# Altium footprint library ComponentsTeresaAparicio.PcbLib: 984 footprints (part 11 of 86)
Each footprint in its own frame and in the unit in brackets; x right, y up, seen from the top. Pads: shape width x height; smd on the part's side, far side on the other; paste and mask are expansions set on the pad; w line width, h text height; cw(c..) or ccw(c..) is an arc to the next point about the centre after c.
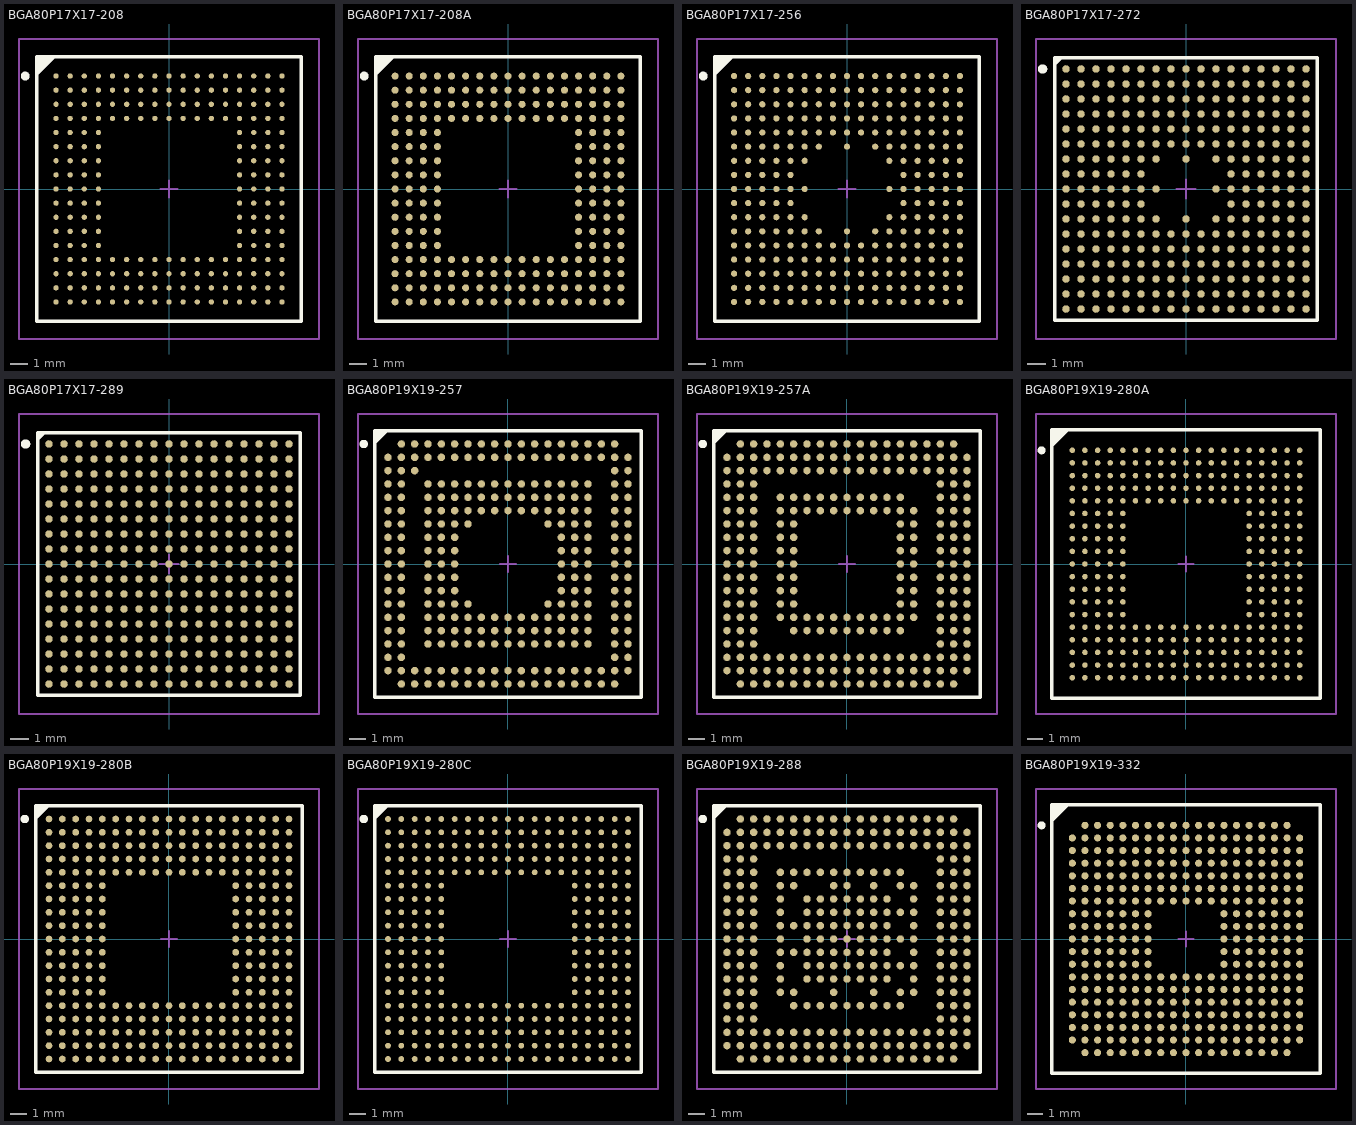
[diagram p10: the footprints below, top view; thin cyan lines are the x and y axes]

## BGA80P17X17-208 [mm] "208-Ball Ball Grid Array 0.8 mm Pitch"
height 1.1
pads (208):
  round 0.3 smd: A1(-6.4,6.4) A2(-5.6,6.4) A3(-4.8,6.4) A4(-4,6.4) A5(-3.2,6.4) A6(-2.4,6.4) A7(-1.6,6.4) A8(-0.8,6.4) A9(0,6.4) A10(0.8,6.4) A11(1.6,6.4) A12(2.4,6.4) A13(3.2,6.4) A14(4,6.4) A15(4.8,6.4) A16(5.6,6.4) A17(6.4,6.4) B1(-6.4,5.6) B2(-5.6,5.6) B3(-4.8,5.6) B4(-4,5.6) B5(-3.2,5.6) B6(-2.4,5.6) B7(-1.6,5.6) B8(-0.8,5.6) B9(0,5.6) B10(0.8,5.6) B11(1.6,5.6) B12(2.4,5.6) B13(3.2,5.6) B14(4,5.6) B15(4.8,5.6) B16(5.6,5.6) B17(6.4,5.6) C1(-6.4,4.8) C2(-5.6,4.8) C3(-4.8,4.8) C4(-4,4.8) C5(-3.2,4.8) C6(-2.4,4.8) C7(-1.6,4.8) C8(-0.8,4.8) C9(0,4.8) C10(0.8,4.8) C11(1.6,4.8) C12(2.4,4.8) C13(3.2,4.8) C14(4,4.8) C15(4.8,4.8) C16(5.6,4.8) C17(6.4,4.8) D1(-6.4,4) D2(-5.6,4) D3(-4.8,4) D4(-4,4) D5(-3.2,4) D6(-2.4,4) D7(-1.6,4) D8(-0.8,4) D9(0,4) D10(0.8,4) D11(1.6,4) D12(2.4,4) D13(3.2,4) D14(4,4) D15(4.8,4) D16(5.6,4) D17(6.4,4) E1(-6.4,3.2) E2(-5.6,3.2) E3(-4.8,3.2) E4(-4,3.2) E14(4,3.2) E15(4.8,3.2) E16(5.6,3.2) E17(6.4,3.2) F1(-6.4,2.4) F2(-5.6,2.4) F3(-4.8,2.4) F4(-4,2.4) F14(4,2.4) F15(4.8,2.4) F16(5.6,2.4) F17(6.4,2.4) G1(-6.4,1.6) G2(-5.6,1.6) G3(-4.8,1.6) G4(-4,1.6) G14(4,1.6) G15(4.8,1.6) G16(5.6,1.6) G17(6.4,1.6) H1(-6.4,0.8) H2(-5.6,0.8) H3(-4.8,0.8) H4(-4,0.8) H14(4,0.8) H15(4.8,0.8) H16(5.6,0.8) H17(6.4,0.8) J1(-6.4,0) J2(-5.6,0) J3(-4.8,0) J4(-4,0) J14(4,0) J15(4.8,0) J16(5.6,0) J17(6.4,0) K1(-6.4,-0.8) K2(-5.6,-0.8) K3(-4.8,-0.8) K4(-4,-0.8) K14(4,-0.8) K15(4.8,-0.8) K16(5.6,-0.8) K17(6.4,-0.8) L1(-6.4,-1.6) L2(-5.6,-1.6) L3(-4.8,-1.6) L4(-4,-1.6) L14(4,-1.6) L15(4.8,-1.6) L16(5.6,-1.6) L17(6.4,-1.6) M1(-6.4,-2.4) M2(-5.6,-2.4) M3(-4.8,-2.4) M4(-4,-2.4) M14(4,-2.4) M15(4.8,-2.4) M16(5.6,-2.4) M17(6.4,-2.4) N1(-6.4,-3.2) N2(-5.6,-3.2) N3(-4.8,-3.2) N4(-4,-3.2) N14(4,-3.2) N15(4.8,-3.2) N16(5.6,-3.2) N17(6.4,-3.2) P1(-6.4,-4) P2(-5.6,-4) P3(-4.8,-4) P4(-4,-4) P5(-3.2,-4) P6(-2.4,-4) P7(-1.6,-4) P8(-0.8,-4) P9(0,-4) P10(0.8,-4) P11(1.6,-4) P12(2.4,-4) P13(3.2,-4) P14(4,-4) P15(4.8,-4) P16(5.6,-4) P17(6.4,-4) R1(-6.4,-4.8) R2(-5.6,-4.8) R3(-4.8,-4.8) R4(-4,-4.8) R5(-3.2,-4.8) R6(-2.4,-4.8) R7(-1.6,-4.8) R8(-0.8,-4.8) R9(0,-4.8) R10(0.8,-4.8) R11(1.6,-4.8) R12(2.4,-4.8) R13(3.2,-4.8) R14(4,-4.8) R15(4.8,-4.8) R16(5.6,-4.8) R17(6.4,-4.8) T1(-6.4,-5.6) T2(-5.6,-5.6) T3(-4.8,-5.6) T4(-4,-5.6) T5(-3.2,-5.6) T6(-2.4,-5.6) T7(-1.6,-5.6) T8(-0.8,-5.6) T9(0,-5.6) T10(0.8,-5.6) T11(1.6,-5.6) T12(2.4,-5.6) T13(3.2,-5.6) T14(4,-5.6) T15(4.8,-5.6) T16(5.6,-5.6) T17(6.4,-5.6) U1(-6.4,-6.4) U2(-5.6,-6.4) U3(-4.8,-6.4) U4(-4,-6.4) U5(-3.2,-6.4) U6(-2.4,-6.4) U7(-1.6,-6.4) U8(-0.8,-6.4) U9(0,-6.4) U10(0.8,-6.4) U11(1.6,-6.4) U12(2.4,-6.4) U13(3.2,-6.4) U14(4,-6.4) U15(4.8,-6.4) U16(5.6,-6.4) U17(6.4,-6.4)
Top Overlay:
  circle w0.25: c-8.15,6.4 r0.125
  region: -6.5,7.5 -7.5,6.5 -7.5,7.5
  lines w0.2: -7.5,6.5 -6.5,7.5 ; -7.5,-7.5 7.5,-7.5 7.5,7.5 -7.5,7.5 -7.5,-7.5
Mechanical 13:
  lines w0.1: -7.5,-7.5 7.5,-7.5 7.5,7.5 -7.5,7.5 -7.5,-7.5
Mechanical 15:
  lines w0.1: -0.5,0 0.5,0 ; 0,-0.5 0,0.5 ; -8.5,-8.5 8.5,-8.5 8.5,8.5 -8.5,8.5 -8.5,-8.5
3D body: height 1.1, standoff 0, extent -7.5,-7.5 7.5,7.5

## BGA80P17X17-208A [mm] "208-Ball Plastic Thin Fine Pitch Ball Grid Array, TFBGA208"
height 1.2
pads (208):
  round 0.4 smd: A1(-6.4,6.4) A2(-5.6,6.4) A3(-4.8,6.4) A4(-4,6.4) A5(-3.2,6.4) A6(-2.4,6.4) A7(-1.6,6.4) A8(-0.8,6.4) A9(0,6.4) A10(0.8,6.4) A11(1.6,6.4) A12(2.4,6.4) A13(3.2,6.4) A14(4,6.4) A15(4.8,6.4) A16(5.6,6.4) A17(6.4,6.4) B1(-6.4,5.6) B2(-5.6,5.6) B3(-4.8,5.6) B4(-4,5.6) B5(-3.2,5.6) B6(-2.4,5.6) B7(-1.6,5.6) B8(-0.8,5.6) B9(0,5.6) B10(0.8,5.6) B11(1.6,5.6) B12(2.4,5.6) B13(3.2,5.6) B14(4,5.6) B15(4.8,5.6) B16(5.6,5.6) B17(6.4,5.6) C1(-6.4,4.8) C2(-5.6,4.8) C3(-4.8,4.8) C4(-4,4.8) C5(-3.2,4.8) C6(-2.4,4.8) C7(-1.6,4.8) C8(-0.8,4.8) C9(0,4.8) C10(0.8,4.8) C11(1.6,4.8) C12(2.4,4.8) C13(3.2,4.8) C14(4,4.8) C15(4.8,4.8) C16(5.6,4.8) C17(6.4,4.8) D1(-6.4,4) D2(-5.6,4) D3(-4.8,4) D4(-4,4) D5(-3.2,4) D6(-2.4,4) D7(-1.6,4) D8(-0.8,4) D9(0,4) D10(0.8,4) D11(1.6,4) D12(2.4,4) D13(3.2,4) D14(4,4) D15(4.8,4) D16(5.6,4) D17(6.4,4) E1(-6.4,3.2) E2(-5.6,3.2) E3(-4.8,3.2) E4(-4,3.2) E14(4,3.2) E15(4.8,3.2) E16(5.6,3.2) E17(6.4,3.2) F1(-6.4,2.4) F2(-5.6,2.4) F3(-4.8,2.4) F4(-4,2.4) F14(4,2.4) F15(4.8,2.4) F16(5.6,2.4) F17(6.4,2.4) G1(-6.4,1.6) G2(-5.6,1.6) G3(-4.8,1.6) G4(-4,1.6) G14(4,1.6) G15(4.8,1.6) G16(5.6,1.6) G17(6.4,1.6) H1(-6.4,0.8) H2(-5.6,0.8) H3(-4.8,0.8) H4(-4,0.8) H14(4,0.8) H15(4.8,0.8) H16(5.6,0.8) H17(6.4,0.8) J1(-6.4,0) J2(-5.6,0) J3(-4.8,0) J4(-4,0) J14(4,0) J15(4.8,0) J16(5.6,0) J17(6.4,0) K1(-6.4,-0.8) K2(-5.6,-0.8) K3(-4.8,-0.8) K4(-4,-0.8) K14(4,-0.8) K15(4.8,-0.8) K16(5.6,-0.8) K17(6.4,-0.8) L1(-6.4,-1.6) L2(-5.6,-1.6) L3(-4.8,-1.6) L4(-4,-1.6) L14(4,-1.6) L15(4.8,-1.6) L16(5.6,-1.6) L17(6.4,-1.6) M1(-6.4,-2.4) M2(-5.6,-2.4) M3(-4.8,-2.4) M4(-4,-2.4) M14(4,-2.4) M15(4.8,-2.4) M16(5.6,-2.4) M17(6.4,-2.4) N1(-6.4,-3.2) N2(-5.6,-3.2) N3(-4.8,-3.2) N4(-4,-3.2) N14(4,-3.2) N15(4.8,-3.2) N16(5.6,-3.2) N17(6.4,-3.2) P1(-6.4,-4) P2(-5.6,-4) P3(-4.8,-4) P4(-4,-4) P5(-3.2,-4) P6(-2.4,-4) P7(-1.6,-4) P8(-0.8,-4) P9(0,-4) P10(0.8,-4) P11(1.6,-4) P12(2.4,-4) P13(3.2,-4) P14(4,-4) P15(4.8,-4) P16(5.6,-4) P17(6.4,-4) R1(-6.4,-4.8) R2(-5.6,-4.8) R3(-4.8,-4.8) R4(-4,-4.8) R5(-3.2,-4.8) R6(-2.4,-4.8) R7(-1.6,-4.8) R8(-0.8,-4.8) R9(0,-4.8) R10(0.8,-4.8) R11(1.6,-4.8) R12(2.4,-4.8) R13(3.2,-4.8) R14(4,-4.8) R15(4.8,-4.8) R16(5.6,-4.8) R17(6.4,-4.8) T1(-6.4,-5.6) T2(-5.6,-5.6) T3(-4.8,-5.6) T4(-4,-5.6) T5(-3.2,-5.6) T6(-2.4,-5.6) T7(-1.6,-5.6) T8(-0.8,-5.6) T9(0,-5.6) T10(0.8,-5.6) T11(1.6,-5.6) T12(2.4,-5.6) T13(3.2,-5.6) T14(4,-5.6) T15(4.8,-5.6) T16(5.6,-5.6) T17(6.4,-5.6) U1(-6.4,-6.4) U2(-5.6,-6.4) U3(-4.8,-6.4) U4(-4,-6.4) U5(-3.2,-6.4) U6(-2.4,-6.4) U7(-1.6,-6.4) U8(-0.8,-6.4) U9(0,-6.4) U10(0.8,-6.4) U11(1.6,-6.4) U12(2.4,-6.4) U13(3.2,-6.4) U14(4,-6.4) U15(4.8,-6.4) U16(5.6,-6.4) U17(6.4,-6.4)
Top Overlay:
  circle w0.25: c-8.15,6.4 r0.125
  region: -6.5,7.5 -7.5,6.5 -7.5,7.5
  lines w0.2: -7.5,6.5 -6.5,7.5 ; -7.5,-7.5 7.5,-7.5 7.5,7.5 -7.5,7.5 -7.5,-7.5
Mechanical 13:
  lines w0.1: -7.5,-7.5 7.5,-7.5 7.5,7.5 -7.5,7.5 -7.5,-7.5
Mechanical 15:
  lines w0.1: -0.5,0 0.5,0 ; 0,-0.5 0,0.5 ; -8.5,-8.5 8.5,-8.5 8.5,8.5 -8.5,8.5 -8.5,-8.5
3D body: height 1.1, standoff 0, extent -7.5,-7.5 7.5,7.5

## BGA80P17X17-256 [mm] "BGA, 256-Leads, Body 15x15mm, Pitch 0.8mm"
height 1.25
pads (256):
  round 0.35 smd: A1(-6.4,6.4) A2(-5.6,6.4) A3(-4.8,6.4) A4(-4,6.4) A5(-3.2,6.4) A6(-2.4,6.4) A7(-1.6,6.4) A8(-0.8,6.4) A9(0,6.4) A10(0.8,6.4) A11(1.6,6.4) A12(2.4,6.4) A13(3.2,6.4) A14(4,6.4) A15(4.8,6.4) A16(5.6,6.4) A17(6.4,6.4) B1(-6.4,5.6) B2(-5.6,5.6) B3(-4.8,5.6) B4(-4,5.6) B5(-3.2,5.6) B6(-2.4,5.6) B7(-1.6,5.6) B8(-0.8,5.6) B9(0,5.6) B10(0.8,5.6) B11(1.6,5.6) B12(2.4,5.6) B13(3.2,5.6) B14(4,5.6) B15(4.8,5.6) B16(5.6,5.6) B17(6.4,5.6) C1(-6.4,4.8) C2(-5.6,4.8) C3(-4.8,4.8) C4(-4,4.8) C5(-3.2,4.8) C6(-2.4,4.8) C7(-1.6,4.8) C8(-0.8,4.8) C9(0,4.8) C10(0.8,4.8) C11(1.6,4.8) C12(2.4,4.8) C13(3.2,4.8) C14(4,4.8) C15(4.8,4.8) C16(5.6,4.8) C17(6.4,4.8) D1(-6.4,4) D2(-5.6,4) D3(-4.8,4) D4(-4,4) D5(-3.2,4) D6(-2.4,4) D7(-1.6,4) D8(-0.8,4) D9(0,4) D10(0.8,4) D11(1.6,4) D12(2.4,4) D13(3.2,4) D14(4,4) D15(4.8,4) D16(5.6,4) D17(6.4,4) E1(-6.4,3.2) E2(-5.6,3.2) E3(-4.8,3.2) E4(-4,3.2) E5(-3.2,3.2) E6(-2.4,3.2) E7(-1.6,3.2) E8(-0.8,3.2) E9(0,3.2) E10(0.8,3.2) E11(1.6,3.2) E12(2.4,3.2) E13(3.2,3.2) E14(4,3.2) E15(4.8,3.2) E16(5.6,3.2) E17(6.4,3.2) F1(-6.4,2.4) F2(-5.6,2.4) F3(-4.8,2.4) F4(-4,2.4) F5(-3.2,2.4) F6(-2.4,2.4) F7(-1.6,2.4) F9(0,2.4) F11(1.6,2.4) F12(2.4,2.4) F13(3.2,2.4) F14(4,2.4) F15(4.8,2.4) F16(5.6,2.4) F17(6.4,2.4) G1(-6.4,1.6) G2(-5.6,1.6) G3(-4.8,1.6) G4(-4,1.6) G5(-3.2,1.6) G6(-2.4,1.6) G12(2.4,1.6) G13(3.2,1.6) G14(4,1.6) G15(4.8,1.6) G16(5.6,1.6) G17(6.4,1.6) H1(-6.4,0.8) H2(-5.6,0.8) H3(-4.8,0.8) H4(-4,0.8) H5(-3.2,0.8) H13(3.2,0.8) H14(4,0.8) H15(4.8,0.8) H16(5.6,0.8) H17(6.4,0.8) J1(-6.4,0) J2(-5.6,0) J3(-4.8,0) J4(-4,0) J5(-3.2,0) J6(-2.4,0) J12(2.4,0) J13(3.2,0) J14(4,0) J15(4.8,0) J16(5.6,0) J17(6.4,0) K1(-6.4,-0.8) K2(-5.6,-0.8) K3(-4.8,-0.8) K4(-4,-0.8) K5(-3.2,-0.8) K13(3.2,-0.8) K14(4,-0.8) K15(4.8,-0.8) K16(5.6,-0.8) K17(6.4,-0.8) L1(-6.4,-1.6) L2(-5.6,-1.6) L3(-4.8,-1.6) L4(-4,-1.6) L5(-3.2,-1.6) L6(-2.4,-1.6) L12(2.4,-1.6) L13(3.2,-1.6) L14(4,-1.6) L15(4.8,-1.6) L16(5.6,-1.6) L17(6.4,-1.6) M1(-6.4,-2.4) M2(-5.6,-2.4) M3(-4.8,-2.4) M4(-4,-2.4) M5(-3.2,-2.4) M6(-2.4,-2.4) M7(-1.6,-2.4) M9(0,-2.4) M11(1.6,-2.4) M12(2.4,-2.4) M13(3.2,-2.4) M14(4,-2.4) M15(4.8,-2.4) M16(5.6,-2.4) M17(6.4,-2.4) N1(-6.4,-3.2) N2(-5.6,-3.2) N3(-4.8,-3.2) N4(-4,-3.2) N5(-3.2,-3.2) N6(-2.4,-3.2) N7(-1.6,-3.2) N8(-0.8,-3.2) N9(0,-3.2) N10(0.8,-3.2) N11(1.6,-3.2) N12(2.4,-3.2) N13(3.2,-3.2) N14(4,-3.2) N15(4.8,-3.2) N16(5.6,-3.2) N17(6.4,-3.2) P1(-6.4,-4) P2(-5.6,-4) P3(-4.8,-4) P4(-4,-4) P5(-3.2,-4) P6(-2.4,-4) P7(-1.6,-4) P8(-0.8,-4) P9(0,-4) P10(0.8,-4) P11(1.6,-4) P12(2.4,-4) P13(3.2,-4) P14(4,-4) P15(4.8,-4) P16(5.6,-4) P17(6.4,-4) R1(-6.4,-4.8) R2(-5.6,-4.8) R3(-4.8,-4.8) R4(-4,-4.8) R5(-3.2,-4.8) R6(-2.4,-4.8) R7(-1.6,-4.8) R8(-0.8,-4.8) R9(0,-4.8) R10(0.8,-4.8) R11(1.6,-4.8) R12(2.4,-4.8) R13(3.2,-4.8) R14(4,-4.8) R15(4.8,-4.8) R16(5.6,-4.8) R17(6.4,-4.8) T1(-6.4,-5.6) T2(-5.6,-5.6) T3(-4.8,-5.6) T4(-4,-5.6) T5(-3.2,-5.6) T6(-2.4,-5.6) T7(-1.6,-5.6) T8(-0.8,-5.6) T9(0,-5.6) T10(0.8,-5.6) T11(1.6,-5.6) T12(2.4,-5.6) T13(3.2,-5.6) T14(4,-5.6) T15(4.8,-5.6) T16(5.6,-5.6) T17(6.4,-5.6) U1(-6.4,-6.4) U2(-5.6,-6.4) U3(-4.8,-6.4) U4(-4,-6.4) U5(-3.2,-6.4) U6(-2.4,-6.4) U7(-1.6,-6.4) U8(-0.8,-6.4) U9(0,-6.4) U10(0.8,-6.4) U11(1.6,-6.4) U12(2.4,-6.4) U13(3.2,-6.4) U14(4,-6.4) U15(4.8,-6.4) U16(5.6,-6.4) U17(6.4,-6.4)
Top Overlay:
  circle w0.25: c-8.15,6.4 r0.125
  region: -6.5,7.5 -7.5,6.5 -7.5,7.5
  lines w0.2: -7.5,6.5 -6.5,7.5 ; -7.5,-7.5 7.5,-7.5 7.5,7.5 -7.5,7.5 -7.5,-7.5
Mechanical 13:
  lines w0.1: -7.5,-7.5 7.5,-7.5 7.5,7.5 -7.5,7.5 -7.5,-7.5
Mechanical 15:
  lines w0.1: -0.5,0 0.5,0 ; 0,-0.5 0,0.5 ; -8.5,-8.5 8.5,-8.5 8.5,8.5 -8.5,8.5 -8.5,-8.5
3D body: height 1.25, standoff 0, extent -7.5,-7.5 7.5,7.5

## BGA80P17X17-272 [mm] "272-Ball Ball Grid Array 0.8 mm Pitch"
height 1.16
pads (272):
  round 0.4 smd: A1(-6.4,6.4) A2(-5.6,6.4) A3(-4.8,6.4) A4(-4,6.4) A5(-3.2,6.4) A6(-2.4,6.4) A7(-1.6,6.4) A8(-0.8,6.4) A9(0,6.4) A10(0.8,6.4) A11(1.6,6.4) A12(2.4,6.4) A13(3.2,6.4) A14(4,6.4) A15(4.8,6.4) A16(5.6,6.4) A17(6.4,6.4) B1(-6.4,5.6) B2(-5.6,5.6) B3(-4.8,5.6) B4(-4,5.6) B5(-3.2,5.6) B6(-2.4,5.6) B7(-1.6,5.6) B8(-0.8,5.6) B9(0,5.6) B10(0.8,5.6) B11(1.6,5.6) B12(2.4,5.6) B13(3.2,5.6) B14(4,5.6) B15(4.8,5.6) B16(5.6,5.6) B17(6.4,5.6) C1(-6.4,4.8) C2(-5.6,4.8) C3(-4.8,4.8) C4(-4,4.8) C5(-3.2,4.8) C6(-2.4,4.8) C7(-1.6,4.8) C8(-0.8,4.8) C9(0,4.8) C10(0.8,4.8) C11(1.6,4.8) C12(2.4,4.8) C13(3.2,4.8) C14(4,4.8) C15(4.8,4.8) C16(5.6,4.8) C17(6.4,4.8) D1(-6.4,4) D2(-5.6,4) D3(-4.8,4) D4(-4,4) D5(-3.2,4) D6(-2.4,4) D7(-1.6,4) D8(-0.8,4) D9(0,4) D10(0.8,4) D11(1.6,4) D12(2.4,4) D13(3.2,4) D14(4,4) D15(4.8,4) D16(5.6,4) D17(6.4,4) E1(-6.4,3.2) E2(-5.6,3.2) E3(-4.8,3.2) E4(-4,3.2) E5(-3.2,3.2) E6(-2.4,3.2) E7(-1.6,3.2) E8(-0.8,3.2) E9(0,3.2) E10(0.8,3.2) E11(1.6,3.2) E12(2.4,3.2) E13(3.2,3.2) E14(4,3.2) E15(4.8,3.2) E16(5.6,3.2) E17(6.4,3.2) F1(-6.4,2.4) F2(-5.6,2.4) F3(-4.8,2.4) F4(-4,2.4) F5(-3.2,2.4) F6(-2.4,2.4) F7(-1.6,2.4) F8(-0.8,2.4) F9(0,2.4) F10(0.8,2.4) F11(1.6,2.4) F12(2.4,2.4) F13(3.2,2.4) F14(4,2.4) F15(4.8,2.4) F16(5.6,2.4) F17(6.4,2.4) G1(-6.4,1.6) G2(-5.6,1.6) G3(-4.8,1.6) G4(-4,1.6) G5(-3.2,1.6) G6(-2.4,1.6) G7(-1.6,1.6) G9(0,1.6) G11(1.6,1.6) G12(2.4,1.6) G13(3.2,1.6) G14(4,1.6) G15(4.8,1.6) G16(5.6,1.6) G17(6.4,1.6) H1(-6.4,0.8) H2(-5.6,0.8) H3(-4.8,0.8) H4(-4,0.8) H5(-3.2,0.8) H6(-2.4,0.8) H12(2.4,0.8) H13(3.2,0.8) H14(4,0.8) H15(4.8,0.8) H16(5.6,0.8) H17(6.4,0.8) J1(-6.4,0) J2(-5.6,0) J3(-4.8,0) J4(-4,0) J5(-3.2,0) J6(-2.4,0) J7(-1.6,0) J11(1.6,0) J12(2.4,0) J13(3.2,0) J14(4,0) J15(4.8,0) J16(5.6,0) J17(6.4,0) K1(-6.4,-0.8) K2(-5.6,-0.8) K3(-4.8,-0.8) K4(-4,-0.8) K5(-3.2,-0.8) K6(-2.4,-0.8) K12(2.4,-0.8) K13(3.2,-0.8) K14(4,-0.8) K15(4.8,-0.8) K16(5.6,-0.8) K17(6.4,-0.8) L1(-6.4,-1.6) L2(-5.6,-1.6) L3(-4.8,-1.6) L4(-4,-1.6) L5(-3.2,-1.6) L6(-2.4,-1.6) L7(-1.6,-1.6) L9(0,-1.6) L11(1.6,-1.6) L12(2.4,-1.6) L13(3.2,-1.6) L14(4,-1.6) L15(4.8,-1.6) L16(5.6,-1.6) L17(6.4,-1.6) M1(-6.4,-2.4) M2(-5.6,-2.4) M3(-4.8,-2.4) M4(-4,-2.4) M5(-3.2,-2.4) M6(-2.4,-2.4) M7(-1.6,-2.4) M8(-0.8,-2.4) M9(0,-2.4) M10(0.8,-2.4) M11(1.6,-2.4) M12(2.4,-2.4) M13(3.2,-2.4) M14(4,-2.4) M15(4.8,-2.4) M16(5.6,-2.4) M17(6.4,-2.4) N1(-6.4,-3.2) N2(-5.6,-3.2) N3(-4.8,-3.2) N4(-4,-3.2) N5(-3.2,-3.2) N6(-2.4,-3.2) N7(-1.6,-3.2) N8(-0.8,-3.2) N9(0,-3.2) N10(0.8,-3.2) N11(1.6,-3.2) N12(2.4,-3.2) N13(3.2,-3.2) N14(4,-3.2) N15(4.8,-3.2) N16(5.6,-3.2) N17(6.4,-3.2) P1(-6.4,-4) P2(-5.6,-4) P3(-4.8,-4) P4(-4,-4) P5(-3.2,-4) P6(-2.4,-4) P7(-1.6,-4) P8(-0.8,-4) P9(0,-4) P10(0.8,-4) P11(1.6,-4) P12(2.4,-4) P13(3.2,-4) P14(4,-4) P15(4.8,-4) P16(5.6,-4) P17(6.4,-4) R1(-6.4,-4.8) R2(-5.6,-4.8) R3(-4.8,-4.8) R4(-4,-4.8) R5(-3.2,-4.8) R6(-2.4,-4.8) R7(-1.6,-4.8) R8(-0.8,-4.8) R9(0,-4.8) R10(0.8,-4.8) R11(1.6,-4.8) R12(2.4,-4.8) R13(3.2,-4.8) R14(4,-4.8) R15(4.8,-4.8) R16(5.6,-4.8) R17(6.4,-4.8) T1(-6.4,-5.6) T2(-5.6,-5.6) T3(-4.8,-5.6) T4(-4,-5.6) T5(-3.2,-5.6) T6(-2.4,-5.6) T7(-1.6,-5.6) T8(-0.8,-5.6) T9(0,-5.6) T10(0.8,-5.6) T11(1.6,-5.6) T12(2.4,-5.6) T13(3.2,-5.6) T14(4,-5.6) T15(4.8,-5.6) T16(5.6,-5.6) T17(6.4,-5.6) U1(-6.4,-6.4) U2(-5.6,-6.4) U3(-4.8,-6.4) U4(-4,-6.4) U5(-3.2,-6.4) U6(-2.4,-6.4) U7(-1.6,-6.4) U8(-0.8,-6.4) U9(0,-6.4) U10(0.8,-6.4) U11(1.6,-6.4) U12(2.4,-6.4) U13(3.2,-6.4) U14(4,-6.4) U15(4.8,-6.4) U16(5.6,-6.4) U17(6.4,-6.4)
Top Overlay:
  circle w0.25: c-7.65,6.4 r0.125
  region: -6.649,7 -7,6.649 -7,7
  lines w0.2: -7,6.649 -6.649,7 ; -7,-7 7,-7 7,7 -7,7 -7,-7
Mechanical 13:
  lines w0.1: -7,-7 7,-7 7,7 -7,7 -7,-7
Mechanical 15:
  lines w0.1: -0.5,0 0.5,0 ; 0,-0.5 0,0.5 ; -8,-8 8,-8 8,8 -8,8 -8,-8
3D body: height 1.16, standoff 0, extent -7,-7 7,7

## BGA80P17X17-289 [mm] "BGA, 289-Leads, Body 14x14mm, Pitch 0.8mm"
height 1.22
pads (289):
  round 0.4 smd: A1(-6.4,6.4) A2(-5.6,6.4) A3(-4.8,6.4) A4(-4,6.4) A5(-3.2,6.4) A6(-2.4,6.4) A7(-1.6,6.4) A8(-0.8,6.4) A9(0,6.4) A10(0.8,6.4) A11(1.6,6.4) A12(2.4,6.4) A13(3.2,6.4) A14(4,6.4) A15(4.8,6.4) A16(5.6,6.4) A17(6.4,6.4) B1(-6.4,5.6) B2(-5.6,5.6) B3(-4.8,5.6) B4(-4,5.6) B5(-3.2,5.6) B6(-2.4,5.6) B7(-1.6,5.6) B8(-0.8,5.6) B9(0,5.6) B10(0.8,5.6) B11(1.6,5.6) B12(2.4,5.6) B13(3.2,5.6) B14(4,5.6) B15(4.8,5.6) B16(5.6,5.6) B17(6.4,5.6) C1(-6.4,4.8) C2(-5.6,4.8) C3(-4.8,4.8) C4(-4,4.8) C5(-3.2,4.8) C6(-2.4,4.8) C7(-1.6,4.8) C8(-0.8,4.8) C9(0,4.8) C10(0.8,4.8) C11(1.6,4.8) C12(2.4,4.8) C13(3.2,4.8) C14(4,4.8) C15(4.8,4.8) C16(5.6,4.8) C17(6.4,4.8) D1(-6.4,4) D2(-5.6,4) D3(-4.8,4) D4(-4,4) D5(-3.2,4) D6(-2.4,4) D7(-1.6,4) D8(-0.8,4) D9(0,4) D10(0.8,4) D11(1.6,4) D12(2.4,4) D13(3.2,4) D14(4,4) D15(4.8,4) D16(5.6,4) D17(6.4,4) E1(-6.4,3.2) E2(-5.6,3.2) E3(-4.8,3.2) E4(-4,3.2) E5(-3.2,3.2) E6(-2.4,3.2) E7(-1.6,3.2) E8(-0.8,3.2) E9(0,3.2) E10(0.8,3.2) E11(1.6,3.2) E12(2.4,3.2) E13(3.2,3.2) E14(4,3.2) E15(4.8,3.2) E16(5.6,3.2) E17(6.4,3.2) F1(-6.4,2.4) F2(-5.6,2.4) F3(-4.8,2.4) F4(-4,2.4) F5(-3.2,2.4) F6(-2.4,2.4) F7(-1.6,2.4) F8(-0.8,2.4) F9(0,2.4) F10(0.8,2.4) F11(1.6,2.4) F12(2.4,2.4) F13(3.2,2.4) F14(4,2.4) F15(4.8,2.4) F16(5.6,2.4) F17(6.4,2.4) G1(-6.4,1.6) G2(-5.6,1.6) G3(-4.8,1.6) G4(-4,1.6) G5(-3.2,1.6) G6(-2.4,1.6) G7(-1.6,1.6) G8(-0.8,1.6) G9(0,1.6) G10(0.8,1.6) G11(1.6,1.6) G12(2.4,1.6) G13(3.2,1.6) G14(4,1.6) G15(4.8,1.6) G16(5.6,1.6) G17(6.4,1.6) H1(-6.4,0.8) H2(-5.6,0.8) H3(-4.8,0.8) H4(-4,0.8) H5(-3.2,0.8) H6(-2.4,0.8) H7(-1.6,0.8) H8(-0.8,0.8) H9(0,0.8) H10(0.8,0.8) H11(1.6,0.8) H12(2.4,0.8) H13(3.2,0.8) H14(4,0.8) H15(4.8,0.8) H16(5.6,0.8) H17(6.4,0.8) J1(-6.4,0) J2(-5.6,0) J3(-4.8,0) J4(-4,0) J5(-3.2,0) J6(-2.4,0) J7(-1.6,0) J8(-0.8,0) J9(0,0) J10(0.8,0) J11(1.6,0) J12(2.4,0) J13(3.2,0) J14(4,0) J15(4.8,0) J16(5.6,0) J17(6.4,0) K1(-6.4,-0.8) K2(-5.6,-0.8) K3(-4.8,-0.8) K4(-4,-0.8) K5(-3.2,-0.8) K6(-2.4,-0.8) K7(-1.6,-0.8) K8(-0.8,-0.8) K9(0,-0.8) K10(0.8,-0.8) K11(1.6,-0.8) K12(2.4,-0.8) K13(3.2,-0.8) K14(4,-0.8) K15(4.8,-0.8) K16(5.6,-0.8) K17(6.4,-0.8) L1(-6.4,-1.6) L2(-5.6,-1.6) L3(-4.8,-1.6) L4(-4,-1.6) L5(-3.2,-1.6) L6(-2.4,-1.6) L7(-1.6,-1.6) L8(-0.8,-1.6) L9(0,-1.6) L10(0.8,-1.6) L11(1.6,-1.6) L12(2.4,-1.6) L13(3.2,-1.6) L14(4,-1.6) L15(4.8,-1.6) L16(5.6,-1.6) L17(6.4,-1.6) M1(-6.4,-2.4) M2(-5.6,-2.4) M3(-4.8,-2.4) M4(-4,-2.4) M5(-3.2,-2.4) M6(-2.4,-2.4) M7(-1.6,-2.4) M8(-0.8,-2.4) M9(0,-2.4) M10(0.8,-2.4) M11(1.6,-2.4) M12(2.4,-2.4) M13(3.2,-2.4) M14(4,-2.4) M15(4.8,-2.4) M16(5.6,-2.4) M17(6.4,-2.4) N1(-6.4,-3.2) N2(-5.6,-3.2) N3(-4.8,-3.2) N4(-4,-3.2) N5(-3.2,-3.2) N6(-2.4,-3.2) N7(-1.6,-3.2) N8(-0.8,-3.2) N9(0,-3.2) N10(0.8,-3.2) N11(1.6,-3.2) N12(2.4,-3.2) N13(3.2,-3.2) N14(4,-3.2) N15(4.8,-3.2) N16(5.6,-3.2) N17(6.4,-3.2) P1(-6.4,-4) P2(-5.6,-4) P3(-4.8,-4) P4(-4,-4) P5(-3.2,-4) P6(-2.4,-4) P7(-1.6,-4) P8(-0.8,-4) P9(0,-4) P10(0.8,-4) P11(1.6,-4) P12(2.4,-4) P13(3.2,-4) P14(4,-4) P15(4.8,-4) P16(5.6,-4) P17(6.4,-4) R1(-6.4,-4.8) R2(-5.6,-4.8) R3(-4.8,-4.8) R4(-4,-4.8) R5(-3.2,-4.8) R6(-2.4,-4.8) R7(-1.6,-4.8) R8(-0.8,-4.8) R9(0,-4.8) R10(0.8,-4.8) R11(1.6,-4.8) R12(2.4,-4.8) R13(3.2,-4.8) R14(4,-4.8) R15(4.8,-4.8) R16(5.6,-4.8) R17(6.4,-4.8) T1(-6.4,-5.6) T2(-5.6,-5.6) T3(-4.8,-5.6) T4(-4,-5.6) T5(-3.2,-5.6) T6(-2.4,-5.6) T7(-1.6,-5.6) T8(-0.8,-5.6) T9(0,-5.6) T10(0.8,-5.6) T11(1.6,-5.6) T12(2.4,-5.6) T13(3.2,-5.6) T14(4,-5.6) T15(4.8,-5.6) T16(5.6,-5.6) T17(6.4,-5.6) U1(-6.4,-6.4) U2(-5.6,-6.4) U3(-4.8,-6.4) U4(-4,-6.4) U5(-3.2,-6.4) U6(-2.4,-6.4) U7(-1.6,-6.4) U8(-0.8,-6.4) U9(0,-6.4) U10(0.8,-6.4) U11(1.6,-6.4) U12(2.4,-6.4) U13(3.2,-6.4) U14(4,-6.4) U15(4.8,-6.4) U16(5.6,-6.4) U17(6.4,-6.4)
Top Overlay:
  circle w0.25: c-7.65,6.4 r0.125
  region: -6.649,7 -7,6.649 -7,7
  lines w0.2: -7,6.649 -6.649,7 ; -7,-7 -7,7 7,7 7,-7 -7,-7
Mechanical 13:
  lines w0.1: -7,-7 -7,7 7,7 7,-7 -7,-7
Mechanical 15:
  lines w0.1: -0.5,0 0.5,0 ; 0,-0.5 0,0.5 ; -8,-8 -8,8 8,8 8,-8 -8,-8
3D body: height 1.22, standoff 0, extent -6.999,-6.999 6.999,6.999

## BGA80P19X19-257 [mm] "257-Ball Ball Grid Array 0.8 mm Pitch"
height 1.4
pads (257):
  round 0.45 smd: A2(-6.4,7.2) A3(-5.6,7.2) A4(-4.8,7.2) A5(-4,7.2) A6(-3.2,7.2) A7(-2.4,7.2) A8(-1.6,7.2) A9(-0.8,7.2) A10(0,7.2) A11(0.8,7.2) A12(1.6,7.2) A13(2.4,7.2) A14(3.2,7.2) A15(4,7.2) A16(4.8,7.2) A17(5.6,7.2) A18(6.4,7.2) B1(-7.2,6.4) B2(-6.4,6.4) B3(-5.6,6.4) B4(-4.8,6.4) B5(-4,6.4) B6(-3.2,6.4) B7(-2.4,6.4) B8(-1.6,6.4) B9(-0.8,6.4) B10(0,6.4) B11(0.8,6.4) B12(1.6,6.4) B13(2.4,6.4) B14(3.2,6.4) B15(4,6.4) B16(4.8,6.4) B17(5.6,6.4) B18(6.4,6.4) B19(7.2,6.4) C1(-7.2,5.6) C2(-6.4,5.6) C3(-5.6,5.6) C18(6.4,5.6) C19(7.2,5.6) D1(-7.2,4.8) D2(-6.4,4.8) D4(-4.8,4.8) D5(-4,4.8) D6(-3.2,4.8) D7(-2.4,4.8) D8(-1.6,4.8) D9(-0.8,4.8) D10(0,4.8) D11(0.8,4.8) D12(1.6,4.8) D13(2.4,4.8) D14(3.2,4.8) D15(4,4.8) D16(4.8,4.8) D18(6.4,4.8) D19(7.2,4.8) E1(-7.2,4) E2(-6.4,4) E4(-4.8,4) E5(-4,4) E6(-3.2,4) E7(-2.4,4) E8(-1.6,4) E9(-0.8,4) E10(0,4) E11(0.8,4) E12(1.6,4) E13(2.4,4) E14(3.2,4) E15(4,4) E16(4.8,4) E18(6.4,4) E19(7.2,4) F1(-7.2,3.2) F2(-6.4,3.2) F4(-4.8,3.2) F5(-4,3.2) F6(-3.2,3.2) F7(-2.4,3.2) F8(-1.6,3.2) F9(-0.8,3.2) F10(0,3.2) F11(0.8,3.2) F12(1.6,3.2) F13(2.4,3.2) F14(3.2,3.2) F15(4,3.2) F16(4.8,3.2) F18(6.4,3.2) F19(7.2,3.2) G1(-7.2,2.4) G2(-6.4,2.4) G4(-4.8,2.4) G5(-4,2.4) G6(-3.2,2.4) G7(-2.4,2.4) G13(2.4,2.4) G14(3.2,2.4) G15(4,2.4) G16(4.8,2.4) G18(6.4,2.4) G19(7.2,2.4) H1(-7.2,1.6) H2(-6.4,1.6) H4(-4.8,1.6) H5(-4,1.6) H6(-3.2,1.6) H14(3.2,1.6) H15(4,1.6) H16(4.8,1.6) H18(6.4,1.6) H19(7.2,1.6) J1(-7.2,0.8) J2(-6.4,0.8) J4(-4.8,0.8) J5(-4,0.8) J6(-3.2,0.8) J14(3.2,0.8) J15(4,0.8) J16(4.8,0.8) J18(6.4,0.8) J19(7.2,0.8) K1(-7.2,0) K2(-6.4,0) K4(-4.8,0) K5(-4,0) K6(-3.2,0) K14(3.2,0) K15(4,0) K16(4.8,0) K18(6.4,0) K19(7.2,0) L1(-7.2,-0.8) L2(-6.4,-0.8) L4(-4.8,-0.8) L5(-4,-0.8) L6(-3.2,-0.8) L14(3.2,-0.8) L15(4,-0.8) L16(4.8,-0.8) L18(6.4,-0.8) L19(7.2,-0.8) M1(-7.2,-1.6) M2(-6.4,-1.6) M4(-4.8,-1.6) M5(-4,-1.6) M6(-3.2,-1.6) M14(3.2,-1.6) M15(4,-1.6) M16(4.8,-1.6) M18(6.4,-1.6) M19(7.2,-1.6) N1(-7.2,-2.4) N2(-6.4,-2.4) N4(-4.8,-2.4) N5(-4,-2.4) N6(-3.2,-2.4) N7(-2.4,-2.4) N13(2.4,-2.4) N14(3.2,-2.4) N15(4,-2.4) N16(4.8,-2.4) N18(6.4,-2.4) N19(7.2,-2.4) P1(-7.2,-3.2) P2(-6.4,-3.2) P4(-4.8,-3.2) P5(-4,-3.2) P6(-3.2,-3.2) P7(-2.4,-3.2) P8(-1.6,-3.2) P9(-0.8,-3.2) P10(0,-3.2) P11(0.8,-3.2) P12(1.6,-3.2) P13(2.4,-3.2) P14(3.2,-3.2) P15(4,-3.2) P16(4.8,-3.2) P18(6.4,-3.2) P19(7.2,-3.2) R1(-7.2,-4) R2(-6.4,-4) R4(-4.8,-4) R5(-4,-4) R6(-3.2,-4) R7(-2.4,-4) R8(-1.6,-4) R9(-0.8,-4) R10(0,-4) R11(0.8,-4) R12(1.6,-4) R13(2.4,-4) R14(3.2,-4) R15(4,-4) R16(4.8,-4) R18(6.4,-4) R19(7.2,-4) T1(-7.2,-4.8) T2(-6.4,-4.8) T4(-4.8,-4.8) T5(-4,-4.8) T6(-3.2,-4.8) T7(-2.4,-4.8) T8(-1.6,-4.8) T9(-0.8,-4.8) T10(0,-4.8) T11(0.8,-4.8) T12(1.6,-4.8) T13(2.4,-4.8) T14(3.2,-4.8) T15(4,-4.8) T16(4.8,-4.8) T18(6.4,-4.8) T19(7.2,-4.8) U1(-7.2,-5.6) U2(-6.4,-5.6) U18(6.4,-5.6) U19(7.2,-5.6) V1(-7.2,-6.4) V2(-6.4,-6.4) V3(-5.6,-6.4) V4(-4.8,-6.4) V5(-4,-6.4) V6(-3.2,-6.4) V7(-2.4,-6.4) V8(-1.6,-6.4) V9(-0.8,-6.4) V10(0,-6.4) V11(0.8,-6.4) V12(1.6,-6.4) V13(2.4,-6.4) V14(3.2,-6.4) V15(4,-6.4) V16(4.8,-6.4) V17(5.6,-6.4) V18(6.4,-6.4) V19(7.2,-6.4) W2(-6.4,-7.2) W3(-5.6,-7.2) W4(-4.8,-7.2) W5(-4,-7.2) W6(-3.2,-7.2) W7(-2.4,-7.2) W8(-1.6,-7.2) W9(-0.8,-7.2) W10(0,-7.2) W11(0.8,-7.2) W12(1.6,-7.2) W13(2.4,-7.2) W14(3.2,-7.2) W15(4,-7.2) W16(4.8,-7.2) W17(5.6,-7.2) W18(6.4,-7.2)
Top Overlay:
  circle w0.25: c-8.65,7.2 r0.125
  region: -7.284,8 -8,7.284 -8,8
  lines w0.2: -8,7.284 -7.284,8 ; -8,-8 -8,8 8,8 8,-8 -8,-8
Mechanical 13:
  lines w0.1: -8,-8 -8,8 8,8 8,-8 -8,-8
Mechanical 15:
  lines w0.1: -0.5,0 0.5,0 ; 0,-0.5 0,0.5 ; -9,-9 -9,9 9,9 9,-9 -9,-9
3D body: height 1.4, standoff 0, extent -8,-8 8,8

## BGA80P19X19-257A [mm] "257-Ball Plastic Ball Grid Array 0.8 mm Pitch"
height 1.4
pads (257):
  round 0.45 smd: A2(-6.4,7.2) A3(-5.6,7.2) A4(-4.8,7.2) A5(-4,7.2) A6(-3.2,7.2) A7(-2.4,7.2) A8(-1.6,7.2) A9(-0.8,7.2) A10(0,7.2) A11(0.8,7.2) A12(1.6,7.2) A13(2.4,7.2) A14(3.2,7.2) A15(4,7.2) A16(4.8,7.2) A17(5.6,7.2) A18(6.4,7.2) B1(-7.2,6.4) B2(-6.4,6.4) B3(-5.6,6.4) B4(-4.8,6.4) B5(-4,6.4) B6(-3.2,6.4) B7(-2.4,6.4) B8(-1.6,6.4) B9(-0.8,6.4) B10(0,6.4) B11(0.8,6.4) B12(1.6,6.4) B13(2.4,6.4) B14(3.2,6.4) B15(4,6.4) B16(4.8,6.4) B17(5.6,6.4) B18(6.4,6.4) B19(7.2,6.4) C1(-7.2,5.6) C2(-6.4,5.6) C3(-5.6,5.6) C4(-4.8,5.6) C5(-4,5.6) C6(-3.2,5.6) C7(-2.4,5.6) C8(-1.6,5.6) C9(-0.8,5.6) C10(0,5.6) C11(0.8,5.6) C12(1.6,5.6) C13(2.4,5.6) C14(3.2,5.6) C15(4,5.6) C16(4.8,5.6) C17(5.6,5.6) C18(6.4,5.6) C19(7.2,5.6) D1(-7.2,4.8) D2(-6.4,4.8) D3(-5.6,4.8) D17(5.6,4.8) D18(6.4,4.8) D19(7.2,4.8) E1(-7.2,4) E2(-6.4,4) E3(-5.6,4) E5(-4,4) E6(-3.2,4) E7(-2.4,4) E8(-1.6,4) E9(-0.8,4) E10(0,4) E11(0.8,4) E12(1.6,4) E13(2.4,4) E14(3.2,4) E17(5.6,4) E18(6.4,4) E19(7.2,4) F1(-7.2,3.2) F2(-6.4,3.2) F3(-5.6,3.2) F5(-4,3.2) F6(-3.2,3.2) F7(-2.4,3.2) F8(-1.6,3.2) F9(-0.8,3.2) F10(0,3.2) F11(0.8,3.2) F12(1.6,3.2) F13(2.4,3.2) F14(3.2,3.2) F15(4,3.2) F17(5.6,3.2) F18(6.4,3.2) F19(7.2,3.2) G1(-7.2,2.4) G2(-6.4,2.4) G3(-5.6,2.4) G5(-4,2.4) G6(-3.2,2.4) G14(3.2,2.4) G15(4,2.4) G17(5.6,2.4) G18(6.4,2.4) G19(7.2,2.4) H1(-7.2,1.6) H2(-6.4,1.6) H3(-5.6,1.6) H5(-4,1.6) H6(-3.2,1.6) H14(3.2,1.6) H15(4,1.6) H17(5.6,1.6) H18(6.4,1.6) H19(7.2,1.6) J1(-7.2,0.8) J2(-6.4,0.8) J3(-5.6,0.8) J5(-4,0.8) J6(-3.2,0.8) J14(3.2,0.8) J15(4,0.8) J17(5.6,0.8) J18(6.4,0.8) J19(7.2,0.8) K1(-7.2,0) K2(-6.4,0) K3(-5.6,0) K5(-4,0) K6(-3.2,0) K14(3.2,0) K15(4,0) K17(5.6,0) K18(6.4,0) K19(7.2,0) L1(-7.2,-0.8) L2(-6.4,-0.8) L3(-5.6,-0.8) L5(-4,-0.8) L6(-3.2,-0.8) L14(3.2,-0.8) L15(4,-0.8) L17(5.6,-0.8) L18(6.4,-0.8) L19(7.2,-0.8) M1(-7.2,-1.6) M2(-6.4,-1.6) M3(-5.6,-1.6) M5(-4,-1.6) M6(-3.2,-1.6) M14(3.2,-1.6) M15(4,-1.6) M17(5.6,-1.6) M18(6.4,-1.6) M19(7.2,-1.6) N1(-7.2,-2.4) N2(-6.4,-2.4) N3(-5.6,-2.4) N5(-4,-2.4) N6(-3.2,-2.4) N14(3.2,-2.4) N15(4,-2.4) N17(5.6,-2.4) N18(6.4,-2.4) N19(7.2,-2.4) P1(-7.2,-3.2) P2(-6.4,-3.2) P3(-5.6,-3.2) P5(-4,-3.2) P6(-3.2,-3.2) P7(-2.4,-3.2) P8(-1.6,-3.2) P9(-0.8,-3.2) P10(0,-3.2) P11(0.8,-3.2) P12(1.6,-3.2) P13(2.4,-3.2) P14(3.2,-3.2) P15(4,-3.2) P17(5.6,-3.2) P18(6.4,-3.2) P19(7.2,-3.2) R1(-7.2,-4) R2(-6.4,-4) R3(-5.6,-4) R6(-3.2,-4) R7(-2.4,-4) R8(-1.6,-4) R9(-0.8,-4) R10(0,-4) R11(0.8,-4) R12(1.6,-4) R13(2.4,-4) R14(3.2,-4) R17(5.6,-4) R18(6.4,-4) R19(7.2,-4) T1(-7.2,-4.8) T2(-6.4,-4.8) T3(-5.6,-4.8) T17(5.6,-4.8) T18(6.4,-4.8) T19(7.2,-4.8) U1(-7.2,-5.6) U2(-6.4,-5.6) U3(-5.6,-5.6) U4(-4.8,-5.6) U5(-4,-5.6) U6(-3.2,-5.6) U7(-2.4,-5.6) U8(-1.6,-5.6) U9(-0.8,-5.6) U10(0,-5.6) U11(0.8,-5.6) U12(1.6,-5.6) U13(2.4,-5.6) U14(3.2,-5.6) U15(4,-5.6) U16(4.8,-5.6) U17(5.6,-5.6) U18(6.4,-5.6) U19(7.2,-5.6) V1(-7.2,-6.4) V2(-6.4,-6.4) V3(-5.6,-6.4) V4(-4.8,-6.4) V5(-4,-6.4) V6(-3.2,-6.4) V7(-2.4,-6.4) V8(-1.6,-6.4) V9(-0.8,-6.4) V10(0,-6.4) V11(0.8,-6.4) V12(1.6,-6.4) V13(2.4,-6.4) V14(3.2,-6.4) V15(4,-6.4) V16(4.8,-6.4) V17(5.6,-6.4) V18(6.4,-6.4) V19(7.2,-6.4) W2(-6.4,-7.2) W3(-5.6,-7.2) W4(-4.8,-7.2) W5(-4,-7.2) W6(-3.2,-7.2) W7(-2.4,-7.2) W8(-1.6,-7.2) W9(-0.8,-7.2) W10(0,-7.2) W11(0.8,-7.2) W12(1.6,-7.2) W13(2.4,-7.2) W14(3.2,-7.2) W15(4,-7.2) W16(4.8,-7.2) W17(5.6,-7.2) W18(6.4,-7.2)
Top Overlay:
  circle w0.25: c-8.65,7.2 r0.125
  region: -7.284,8 -8,7.284 -8,8
  lines w0.2: -8,7.284 -7.284,8 ; -8,-8 -8,8 8,8 8,-8 -8,-8
Mechanical 13:
  lines w0.1: -8,-8 -8,8 8,8 8,-8 -8,-8
Mechanical 15:
  lines w0.1: -0.5,0 0.5,0 ; 0,-0.5 0,0.5 ; -9,-9 -9,9 9,9 9,-9 -9,-9
3D body: height 1.4, standoff 0, extent -8,-8 8,8

## BGA80P19X19-280A [mm] "280-Ball Ball Grid Array 0.8 mm Pitch"
height 1.5
pads (280):
  round 0.35 smd: A1(-7.2,7.2) A2(-6.4,7.2) A3(-5.6,7.2) A4(-4.8,7.2) A5(-4,7.2) A6(-3.2,7.2) A7(-2.4,7.2) A8(-1.6,7.2) A9(-0.8,7.2) A10(0,7.2) A11(0.8,7.2) A12(1.6,7.2) A13(2.4,7.2) A14(3.2,7.2) A15(4,7.2) A16(4.8,7.2) A17(5.6,7.2) A18(6.4,7.2) A19(7.2,7.2) B1(-7.2,6.4) B2(-6.4,6.4) B3(-5.6,6.4) B4(-4.8,6.4) B5(-4,6.4) B6(-3.2,6.4) B7(-2.4,6.4) B8(-1.6,6.4) B9(-0.8,6.4) B10(0,6.4) B11(0.8,6.4) B12(1.6,6.4) B13(2.4,6.4) B14(3.2,6.4) B15(4,6.4) B16(4.8,6.4) B17(5.6,6.4) B18(6.4,6.4) B19(7.2,6.4) C1(-7.2,5.6) C2(-6.4,5.6) C3(-5.6,5.6) C4(-4.8,5.6) C5(-4,5.6) C6(-3.2,5.6) C7(-2.4,5.6) C8(-1.6,5.6) C9(-0.8,5.6) C10(0,5.6) C11(0.8,5.6) C12(1.6,5.6) C13(2.4,5.6) C14(3.2,5.6) C15(4,5.6) C16(4.8,5.6) C17(5.6,5.6) C18(6.4,5.6) C19(7.2,5.6) D1(-7.2,4.8) D2(-6.4,4.8) D3(-5.6,4.8) D4(-4.8,4.8) D5(-4,4.8) D6(-3.2,4.8) D7(-2.4,4.8) D8(-1.6,4.8) D9(-0.8,4.8) D10(0,4.8) D11(0.8,4.8) D12(1.6,4.8) D13(2.4,4.8) D14(3.2,4.8) D15(4,4.8) D16(4.8,4.8) D17(5.6,4.8) D18(6.4,4.8) D19(7.2,4.8) E1(-7.2,4) E2(-6.4,4) E3(-5.6,4) E4(-4.8,4) E5(-4,4) E6(-3.2,4) E7(-2.4,4) E8(-1.6,4) E9(-0.8,4) E10(0,4) E11(0.8,4) E12(1.6,4) E13(2.4,4) E14(3.2,4) E15(4,4) E16(4.8,4) E17(5.6,4) E18(6.4,4) E19(7.2,4) F1(-7.2,3.2) F2(-6.4,3.2) F3(-5.6,3.2) F4(-4.8,3.2) F5(-4,3.2) F15(4,3.2) F16(4.8,3.2) F17(5.6,3.2) F18(6.4,3.2) F19(7.2,3.2) G1(-7.2,2.4) G2(-6.4,2.4) G3(-5.6,2.4) G4(-4.8,2.4) G5(-4,2.4) G15(4,2.4) G16(4.8,2.4) G17(5.6,2.4) G18(6.4,2.4) G19(7.2,2.4) H1(-7.2,1.6) H2(-6.4,1.6) H3(-5.6,1.6) H4(-4.8,1.6) H5(-4,1.6) H15(4,1.6) H16(4.8,1.6) H17(5.6,1.6) H18(6.4,1.6) H19(7.2,1.6) J1(-7.2,0.8) J2(-6.4,0.8) J3(-5.6,0.8) J4(-4.8,0.8) J5(-4,0.8) J15(4,0.8) J16(4.8,0.8) J17(5.6,0.8) J18(6.4,0.8) J19(7.2,0.8) K1(-7.2,0) K2(-6.4,0) K3(-5.6,0) K4(-4.8,0) K5(-4,0) K15(4,0) K16(4.8,0) K17(5.6,0) K18(6.4,0) K19(7.2,0) L1(-7.2,-0.8) L2(-6.4,-0.8) L3(-5.6,-0.8) L4(-4.8,-0.8) L5(-4,-0.8) L15(4,-0.8) L16(4.8,-0.8) L17(5.6,-0.8) L18(6.4,-0.8) L19(7.2,-0.8) M1(-7.2,-1.6) M2(-6.4,-1.6) M3(-5.6,-1.6) M4(-4.8,-1.6) M5(-4,-1.6) M15(4,-1.6) M16(4.8,-1.6) M17(5.6,-1.6) M18(6.4,-1.6) M19(7.2,-1.6) N1(-7.2,-2.4) N2(-6.4,-2.4) N3(-5.6,-2.4) N4(-4.8,-2.4) N5(-4,-2.4) N15(4,-2.4) N16(4.8,-2.4) N17(5.6,-2.4) N18(6.4,-2.4) N19(7.2,-2.4) P1(-7.2,-3.2) P2(-6.4,-3.2) P3(-5.6,-3.2) P4(-4.8,-3.2) P5(-4,-3.2) P15(4,-3.2) P16(4.8,-3.2) P17(5.6,-3.2) P18(6.4,-3.2) P19(7.2,-3.2) R1(-7.2,-4) R2(-6.4,-4) R3(-5.6,-4) R4(-4.8,-4) R5(-4,-4) R6(-3.2,-4) R7(-2.4,-4) R8(-1.6,-4) R9(-0.8,-4) R10(0,-4) R11(0.8,-4) R12(1.6,-4) R13(2.4,-4) R14(3.2,-4) R15(4,-4) R16(4.8,-4) R17(5.6,-4) R18(6.4,-4) R19(7.2,-4) T1(-7.2,-4.8) T2(-6.4,-4.8) T3(-5.6,-4.8) T4(-4.8,-4.8) T5(-4,-4.8) T6(-3.2,-4.8) T7(-2.4,-4.8) T8(-1.6,-4.8) T9(-0.8,-4.8) T10(0,-4.8) T11(0.8,-4.8) T12(1.6,-4.8) T13(2.4,-4.8) T14(3.2,-4.8) T15(4,-4.8) T16(4.8,-4.8) T17(5.6,-4.8) T18(6.4,-4.8) T19(7.2,-4.8) U1(-7.2,-5.6) U2(-6.4,-5.6) U3(-5.6,-5.6) U4(-4.8,-5.6) U5(-4,-5.6) U6(-3.2,-5.6) U7(-2.4,-5.6) U8(-1.6,-5.6) U9(-0.8,-5.6) U10(0,-5.6) U11(0.8,-5.6) U12(1.6,-5.6) U13(2.4,-5.6) U14(3.2,-5.6) U15(4,-5.6) U16(4.8,-5.6) U17(5.6,-5.6) U18(6.4,-5.6) U19(7.2,-5.6) V1(-7.2,-6.4) V2(-6.4,-6.4) V3(-5.6,-6.4) V4(-4.8,-6.4) V5(-4,-6.4) V6(-3.2,-6.4) V7(-2.4,-6.4) V8(-1.6,-6.4) V9(-0.8,-6.4) V10(0,-6.4) V11(0.8,-6.4) V12(1.6,-6.4) V13(2.4,-6.4) V14(3.2,-6.4) V15(4,-6.4) V16(4.8,-6.4) V17(5.6,-6.4) V18(6.4,-6.4) V19(7.2,-6.4) W1(-7.2,-7.2) W2(-6.4,-7.2) W3(-5.6,-7.2) W4(-4.8,-7.2) W5(-4,-7.2) W6(-3.2,-7.2) W7(-2.4,-7.2) W8(-1.6,-7.2) W9(-0.8,-7.2) W10(0,-7.2) W11(0.8,-7.2) W12(1.6,-7.2) W13(2.4,-7.2) W14(3.2,-7.2) W15(4,-7.2) W16(4.8,-7.2) W17(5.6,-7.2) W18(6.4,-7.2) W19(7.2,-7.2)
Top Overlay:
  circle w0.25: c-9.15,7.2 r0.125
  region: -7.5,8.5 -8.5,7.5 -8.5,8.5
  lines w0.2: -8.5,7.5 -7.5,8.5 ; -8.5,-8.5 -8.5,8.5 8.5,8.5 8.5,-8.5 -8.5,-8.5
Mechanical 13:
  lines w0.1: -8.5,-8.5 -8.5,8.5 8.5,8.5 8.5,-8.5 -8.5,-8.5
Mechanical 15:
  lines w0.1: -0.5,0 0.5,0 ; 0,-0.5 0,0.5 ; -9.5,-9.5 -9.5,9.5 9.5,9.5 9.5,-9.5 -9.5,-9.5
3D body: height 1.5, standoff 0, extent -8.5,-8.5 8.5,8.5

## BGA80P19X19-280B [mm] "280-Ball Chip Scale Ball Grid Array (CS280)"
height 1.2
pads (280):
  round 0.4 smd: A1(-7.2,7.2) A2(-6.4,7.2) A3(-5.6,7.2) A4(-4.8,7.2) A5(-4,7.2) A6(-3.2,7.2) A7(-2.4,7.2) A8(-1.6,7.2) A9(-0.8,7.2) A10(0,7.2) A11(0.8,7.2) A12(1.6,7.2) A13(2.4,7.2) A14(3.2,7.2) A15(4,7.2) A16(4.8,7.2) A17(5.6,7.2) A18(6.4,7.2) A19(7.2,7.2) B1(-7.2,6.4) B2(-6.4,6.4) B3(-5.6,6.4) B4(-4.8,6.4) B5(-4,6.4) B6(-3.2,6.4) B7(-2.4,6.4) B8(-1.6,6.4) B9(-0.8,6.4) B10(0,6.4) B11(0.8,6.4) B12(1.6,6.4) B13(2.4,6.4) B14(3.2,6.4) B15(4,6.4) B16(4.8,6.4) B17(5.6,6.4) B18(6.4,6.4) B19(7.2,6.4) C1(-7.2,5.6) C2(-6.4,5.6) C3(-5.6,5.6) C4(-4.8,5.6) C5(-4,5.6) C6(-3.2,5.6) C7(-2.4,5.6) C8(-1.6,5.6) C9(-0.8,5.6) C10(0,5.6) C11(0.8,5.6) C12(1.6,5.6) C13(2.4,5.6) C14(3.2,5.6) C15(4,5.6) C16(4.8,5.6) C17(5.6,5.6) C18(6.4,5.6) C19(7.2,5.6) D1(-7.2,4.8) D2(-6.4,4.8) D3(-5.6,4.8) D4(-4.8,4.8) D5(-4,4.8) D6(-3.2,4.8) D7(-2.4,4.8) D8(-1.6,4.8) D9(-0.8,4.8) D10(0,4.8) D11(0.8,4.8) D12(1.6,4.8) D13(2.4,4.8) D14(3.2,4.8) D15(4,4.8) D16(4.8,4.8) D17(5.6,4.8) D18(6.4,4.8) D19(7.2,4.8) E1(-7.2,4) E2(-6.4,4) E3(-5.6,4) E4(-4.8,4) E5(-4,4) E6(-3.2,4) E7(-2.4,4) E8(-1.6,4) E9(-0.8,4) E10(0,4) E11(0.8,4) E12(1.6,4) E13(2.4,4) E14(3.2,4) E15(4,4) E16(4.8,4) E17(5.6,4) E18(6.4,4) E19(7.2,4) F1(-7.2,3.2) F2(-6.4,3.2) F3(-5.6,3.2) F4(-4.8,3.2) F5(-4,3.2) F15(4,3.2) F16(4.8,3.2) F17(5.6,3.2) F18(6.4,3.2) F19(7.2,3.2) G1(-7.2,2.4) G2(-6.4,2.4) G3(-5.6,2.4) G4(-4.8,2.4) G5(-4,2.4) G15(4,2.4) G16(4.8,2.4) G17(5.6,2.4) G18(6.4,2.4) G19(7.2,2.4) H1(-7.2,1.6) H2(-6.4,1.6) H3(-5.6,1.6) H4(-4.8,1.6) H5(-4,1.6) H15(4,1.6) H16(4.8,1.6) H17(5.6,1.6) H18(6.4,1.6) H19(7.2,1.6) J1(-7.2,0.8) J2(-6.4,0.8) J3(-5.6,0.8) J4(-4.8,0.8) J5(-4,0.8) J15(4,0.8) J16(4.8,0.8) J17(5.6,0.8) J18(6.4,0.8) J19(7.2,0.8) K1(-7.2,0) K2(-6.4,0) K3(-5.6,0) K4(-4.8,0) K5(-4,0) K15(4,0) K16(4.8,0) K17(5.6,0) K18(6.4,0) K19(7.2,0) L1(-7.2,-0.8) L2(-6.4,-0.8) L3(-5.6,-0.8) L4(-4.8,-0.8) L5(-4,-0.8) L15(4,-0.8) L16(4.8,-0.8) L17(5.6,-0.8) L18(6.4,-0.8) L19(7.2,-0.8) M1(-7.2,-1.6) M2(-6.4,-1.6) M3(-5.6,-1.6) M4(-4.8,-1.6) M5(-4,-1.6) M15(4,-1.6) M16(4.8,-1.6) M17(5.6,-1.6) M18(6.4,-1.6) M19(7.2,-1.6) N1(-7.2,-2.4) N2(-6.4,-2.4) N3(-5.6,-2.4) N4(-4.8,-2.4) N5(-4,-2.4) N15(4,-2.4) N16(4.8,-2.4) N17(5.6,-2.4) N18(6.4,-2.4) N19(7.2,-2.4) P1(-7.2,-3.2) P2(-6.4,-3.2) P3(-5.6,-3.2) P4(-4.8,-3.2) P5(-4,-3.2) P15(4,-3.2) P16(4.8,-3.2) P17(5.6,-3.2) P18(6.4,-3.2) P19(7.2,-3.2) R1(-7.2,-4) R2(-6.4,-4) R3(-5.6,-4) R4(-4.8,-4) R5(-4,-4) R6(-3.2,-4) R7(-2.4,-4) R8(-1.6,-4) R9(-0.8,-4) R10(0,-4) R11(0.8,-4) R12(1.6,-4) R13(2.4,-4) R14(3.2,-4) R15(4,-4) R16(4.8,-4) R17(5.6,-4) R18(6.4,-4) R19(7.2,-4) T1(-7.2,-4.8) T2(-6.4,-4.8) T3(-5.6,-4.8) T4(-4.8,-4.8) T5(-4,-4.8) T6(-3.2,-4.8) T7(-2.4,-4.8) T8(-1.6,-4.8) T9(-0.8,-4.8) T10(0,-4.8) T11(0.8,-4.8) T12(1.6,-4.8) T13(2.4,-4.8) T14(3.2,-4.8) T15(4,-4.8) T16(4.8,-4.8) T17(5.6,-4.8) T18(6.4,-4.8) T19(7.2,-4.8) U1(-7.2,-5.6) U2(-6.4,-5.6) U3(-5.6,-5.6) U4(-4.8,-5.6) U5(-4,-5.6) U6(-3.2,-5.6) U7(-2.4,-5.6) U8(-1.6,-5.6) U9(-0.8,-5.6) U10(0,-5.6) U11(0.8,-5.6) U12(1.6,-5.6) U13(2.4,-5.6) U14(3.2,-5.6) U15(4,-5.6) U16(4.8,-5.6) U17(5.6,-5.6) U18(6.4,-5.6) U19(7.2,-5.6) V1(-7.2,-6.4) V2(-6.4,-6.4) V3(-5.6,-6.4) V4(-4.8,-6.4) V5(-4,-6.4) V6(-3.2,-6.4) V7(-2.4,-6.4) V8(-1.6,-6.4) V9(-0.8,-6.4) V10(0,-6.4) V11(0.8,-6.4) V12(1.6,-6.4) V13(2.4,-6.4) V14(3.2,-6.4) V15(4,-6.4) V16(4.8,-6.4) V17(5.6,-6.4) V18(6.4,-6.4) V19(7.2,-6.4) W1(-7.2,-7.2) W2(-6.4,-7.2) W3(-5.6,-7.2) W4(-4.8,-7.2) W5(-4,-7.2) W6(-3.2,-7.2) W7(-2.4,-7.2) W8(-1.6,-7.2) W9(-0.8,-7.2) W10(0,-7.2) W11(0.8,-7.2) W12(1.6,-7.2) W13(2.4,-7.2) W14(3.2,-7.2) W15(4,-7.2) W16(4.8,-7.2) W17(5.6,-7.2) W18(6.4,-7.2) W19(7.2,-7.2)
Top Overlay:
  circle w0.25: c-8.65,7.2 r0.125
  region: -7.249,8 -8,7.249 -8,8
  lines w0.2: -8,7.249 -7.249,8 ; -8,-8 -8,8 8,8 8,-8 -8,-8
Mechanical 13:
  lines w0.1: -8,-8 -8,8 8,8 8,-8 -8,-8
Mechanical 15:
  lines w0.1: -0.5,0 0.5,0 ; 0,-0.5 0,0.5 ; -9,-9 -9,9 9,9 9,-9 -9,-9
3D body: height 1.2, standoff 0, extent -8,-8 8,8

## BGA80P19X19-280C [mm] "280-Ball Chip Scale Ball Grid Array (CS280LAM)"
height 1.2
pads (280):
  round 0.35 smd: A1(-7.2,7.2) A2(-6.4,7.2) A3(-5.6,7.2) A4(-4.8,7.2) A5(-4,7.2) A6(-3.2,7.2) A7(-2.4,7.2) A8(-1.6,7.2) A9(-0.8,7.2) A10(0,7.2) A11(0.8,7.2) A12(1.6,7.2) A13(2.4,7.2) A14(3.2,7.2) A15(4,7.2) A16(4.8,7.2) A17(5.6,7.2) A18(6.4,7.2) A19(7.2,7.2) B1(-7.2,6.4) B2(-6.4,6.4) B3(-5.6,6.4) B4(-4.8,6.4) B5(-4,6.4) B6(-3.2,6.4) B7(-2.4,6.4) B8(-1.6,6.4) B9(-0.8,6.4) B10(0,6.4) B11(0.8,6.4) B12(1.6,6.4) B13(2.4,6.4) B14(3.2,6.4) B15(4,6.4) B16(4.8,6.4) B17(5.6,6.4) B18(6.4,6.4) B19(7.2,6.4) C1(-7.2,5.6) C2(-6.4,5.6) C3(-5.6,5.6) C4(-4.8,5.6) C5(-4,5.6) C6(-3.2,5.6) C7(-2.4,5.6) C8(-1.6,5.6) C9(-0.8,5.6) C10(0,5.6) C11(0.8,5.6) C12(1.6,5.6) C13(2.4,5.6) C14(3.2,5.6) C15(4,5.6) C16(4.8,5.6) C17(5.6,5.6) C18(6.4,5.6) C19(7.2,5.6) D1(-7.2,4.8) D2(-6.4,4.8) D3(-5.6,4.8) D4(-4.8,4.8) D5(-4,4.8) D6(-3.2,4.8) D7(-2.4,4.8) D8(-1.6,4.8) D9(-0.8,4.8) D10(0,4.8) D11(0.8,4.8) D12(1.6,4.8) D13(2.4,4.8) D14(3.2,4.8) D15(4,4.8) D16(4.8,4.8) D17(5.6,4.8) D18(6.4,4.8) D19(7.2,4.8) E1(-7.2,4) E2(-6.4,4) E3(-5.6,4) E4(-4.8,4) E5(-4,4) E6(-3.2,4) E7(-2.4,4) E8(-1.6,4) E9(-0.8,4) E10(0,4) E11(0.8,4) E12(1.6,4) E13(2.4,4) E14(3.2,4) E15(4,4) E16(4.8,4) E17(5.6,4) E18(6.4,4) E19(7.2,4) F1(-7.2,3.2) F2(-6.4,3.2) F3(-5.6,3.2) F4(-4.8,3.2) F5(-4,3.2) F15(4,3.2) F16(4.8,3.2) F17(5.6,3.2) F18(6.4,3.2) F19(7.2,3.2) G1(-7.2,2.4) G2(-6.4,2.4) G3(-5.6,2.4) G4(-4.8,2.4) G5(-4,2.4) G15(4,2.4) G16(4.8,2.4) G17(5.6,2.4) G18(6.4,2.4) G19(7.2,2.4) H1(-7.2,1.6) H2(-6.4,1.6) H3(-5.6,1.6) H4(-4.8,1.6) H5(-4,1.6) H15(4,1.6) H16(4.8,1.6) H17(5.6,1.6) H18(6.4,1.6) H19(7.2,1.6) J1(-7.2,0.8) J2(-6.4,0.8) J3(-5.6,0.8) J4(-4.8,0.8) J5(-4,0.8) J15(4,0.8) J16(4.8,0.8) J17(5.6,0.8) J18(6.4,0.8) J19(7.2,0.8) K1(-7.2,0) K2(-6.4,0) K3(-5.6,0) K4(-4.8,0) K5(-4,0) K15(4,0) K16(4.8,0) K17(5.6,0) K18(6.4,0) K19(7.2,0) L1(-7.2,-0.8) L2(-6.4,-0.8) L3(-5.6,-0.8) L4(-4.8,-0.8) L5(-4,-0.8) L15(4,-0.8) L16(4.8,-0.8) L17(5.6,-0.8) L18(6.4,-0.8) L19(7.2,-0.8) M1(-7.2,-1.6) M2(-6.4,-1.6) M3(-5.6,-1.6) M4(-4.8,-1.6) M5(-4,-1.6) M15(4,-1.6) M16(4.8,-1.6) M17(5.6,-1.6) M18(6.4,-1.6) M19(7.2,-1.6) N1(-7.2,-2.4) N2(-6.4,-2.4) N3(-5.6,-2.4) N4(-4.8,-2.4) N5(-4,-2.4) N15(4,-2.4) N16(4.8,-2.4) N17(5.6,-2.4) N18(6.4,-2.4) N19(7.2,-2.4) P1(-7.2,-3.2) P2(-6.4,-3.2) P3(-5.6,-3.2) P4(-4.8,-3.2) P5(-4,-3.2) P15(4,-3.2) P16(4.8,-3.2) P17(5.6,-3.2) P18(6.4,-3.2) P19(7.2,-3.2) R1(-7.2,-4) R2(-6.4,-4) R3(-5.6,-4) R4(-4.8,-4) R5(-4,-4) R6(-3.2,-4) R7(-2.4,-4) R8(-1.6,-4) R9(-0.8,-4) R10(0,-4) R11(0.8,-4) R12(1.6,-4) R13(2.4,-4) R14(3.2,-4) R15(4,-4) R16(4.8,-4) R17(5.6,-4) R18(6.4,-4) R19(7.2,-4) T1(-7.2,-4.8) T2(-6.4,-4.8) T3(-5.6,-4.8) T4(-4.8,-4.8) T5(-4,-4.8) T6(-3.2,-4.8) T7(-2.4,-4.8) T8(-1.6,-4.8) T9(-0.8,-4.8) T10(0,-4.8) T11(0.8,-4.8) T12(1.6,-4.8) T13(2.4,-4.8) T14(3.2,-4.8) T15(4,-4.8) T16(4.8,-4.8) T17(5.6,-4.8) T18(6.4,-4.8) T19(7.2,-4.8) U1(-7.2,-5.6) U2(-6.4,-5.6) U3(-5.6,-5.6) U4(-4.8,-5.6) U5(-4,-5.6) U6(-3.2,-5.6) U7(-2.4,-5.6) U8(-1.6,-5.6) U9(-0.8,-5.6) U10(0,-5.6) U11(0.8,-5.6) U12(1.6,-5.6) U13(2.4,-5.6) U14(3.2,-5.6) U15(4,-5.6) U16(4.8,-5.6) U17(5.6,-5.6) U18(6.4,-5.6) U19(7.2,-5.6) V1(-7.2,-6.4) V2(-6.4,-6.4) V3(-5.6,-6.4) V4(-4.8,-6.4) V5(-4,-6.4) V6(-3.2,-6.4) V7(-2.4,-6.4) V8(-1.6,-6.4) V9(-0.8,-6.4) V10(0,-6.4) V11(0.8,-6.4) V12(1.6,-6.4) V13(2.4,-6.4) V14(3.2,-6.4) V15(4,-6.4) V16(4.8,-6.4) V17(5.6,-6.4) V18(6.4,-6.4) V19(7.2,-6.4) W1(-7.2,-7.2) W2(-6.4,-7.2) W3(-5.6,-7.2) W4(-4.8,-7.2) W5(-4,-7.2) W6(-3.2,-7.2) W7(-2.4,-7.2) W8(-1.6,-7.2) W9(-0.8,-7.2) W10(0,-7.2) W11(0.8,-7.2) W12(1.6,-7.2) W13(2.4,-7.2) W14(3.2,-7.2) W15(4,-7.2) W16(4.8,-7.2) W17(5.6,-7.2) W18(6.4,-7.2) W19(7.2,-7.2)
Top Overlay:
  circle w0.25: c-8.65,7.2 r0.125
  region: -7.249,8 -8,7.249 -8,8
  lines w0.2: -8,7.249 -7.249,8 ; -8,-8 -8,8 8,8 8,-8 -8,-8
Mechanical 13:
  lines w0.1: -8,-8 -8,8 8,8 8,-8 -8,-8
Mechanical 15:
  lines w0.1: -0.5,0 0.5,0 ; 0,-0.5 0,0.5 ; -9,-9 -9,9 9,9 9,-9 -9,-9
3D body: height 1.2, standoff 0, extent -8,-8 8,8

## BGA80P19X19-288 [mm] "288-Ball Ball Grid Array 0.8 mm Pitch"
height 1.4
pads (288):
  round 0.45 smd: A2(-6.4,7.2) A3(-5.6,7.2) A4(-4.8,7.2) A5(-4,7.2) A6(-3.2,7.2) A7(-2.4,7.2) A8(-1.6,7.2) A9(-0.8,7.2) A10(0,7.2) A11(0.8,7.2) A12(1.6,7.2) A13(2.4,7.2) A14(3.2,7.2) A15(4,7.2) A16(4.8,7.2) A17(5.6,7.2) A18(6.4,7.2) B1(-7.2,6.4) B2(-6.4,6.4) B3(-5.6,6.4) B4(-4.8,6.4) B5(-4,6.4) B6(-3.2,6.4) B7(-2.4,6.4) B8(-1.6,6.4) B9(-0.8,6.4) B10(0,6.4) B11(0.8,6.4) B12(1.6,6.4) B13(2.4,6.4) B14(3.2,6.4) B15(4,6.4) B16(4.8,6.4) B17(5.6,6.4) B18(6.4,6.4) B19(7.2,6.4) C1(-7.2,5.6) C2(-6.4,5.6) C3(-5.6,5.6) C4(-4.8,5.6) C5(-4,5.6) C6(-3.2,5.6) C7(-2.4,5.6) C8(-1.6,5.6) C9(-0.8,5.6) C10(0,5.6) C11(0.8,5.6) C12(1.6,5.6) C13(2.4,5.6) C14(3.2,5.6) C15(4,5.6) C16(4.8,5.6) C17(5.6,5.6) C18(6.4,5.6) C19(7.2,5.6) D1(-7.2,4.8) D2(-6.4,4.8) D3(-5.6,4.8) D17(5.6,4.8) D18(6.4,4.8) D19(7.2,4.8) E1(-7.2,4) E2(-6.4,4) E3(-5.6,4) E5(-4,4) E6(-3.2,4) E7(-2.4,4) E8(-1.6,4) E9(-0.8,4) E10(0,4) E11(0.8,4) E12(1.6,4) E13(2.4,4) E14(3.2,4) E17(5.6,4) E18(6.4,4) E19(7.2,4) F1(-7.2,3.2) F2(-6.4,3.2) F3(-5.6,3.2) F5(-4,3.2) F6(-3.2,3.2) F9(-0.8,3.2) F10(0,3.2) F12(1.6,3.2) F14(3.2,3.2) F15(4,3.2) F17(5.6,3.2) F18(6.4,3.2) F19(7.2,3.2) G1(-7.2,2.4) G2(-6.4,2.4) G3(-5.6,2.4) G5(-4,2.4) G7(-2.4,2.4) G8(-1.6,2.4) G9(-0.8,2.4) G10(0,2.4) G11(0.8,2.4) G12(1.6,2.4) G13(2.4,2.4) G15(4,2.4) G17(5.6,2.4) G18(6.4,2.4) G19(7.2,2.4) H1(-7.2,1.6) H2(-6.4,1.6) H3(-5.6,1.6) H5(-4,1.6) H7(-2.4,1.6) H8(-1.6,1.6) H9(-0.8,1.6) H10(0,1.6) H11(0.8,1.6) H12(1.6,1.6) H13(2.4,1.6) H14(3.2,1.6) H15(4,1.6) H17(5.6,1.6) H18(6.4,1.6) H19(7.2,1.6) J1(-7.2,0.8) J2(-6.4,0.8) J3(-5.6,0.8) J5(-4,0.8) J6(-3.2,0.8) J7(-2.4,0.8) J8(-1.6,0.8) J9(-0.8,0.8) J10(0,0.8) J11(0.8,0.8) J12(1.6,0.8) J13(2.4,0.8) J15(4,0.8) J17(5.6,0.8) J18(6.4,0.8) J19(7.2,0.8) K1(-7.2,0) K2(-6.4,0) K3(-5.6,0) K5(-4,0) K7(-2.4,0) K8(-1.6,0) K9(-0.8,0) K10(0,0) K11(0.8,0) K12(1.6,0) K13(2.4,0) K14(3.2,0) K15(4,0) K17(5.6,0) K18(6.4,0) K19(7.2,0) L1(-7.2,-0.8) L2(-6.4,-0.8) L3(-5.6,-0.8) L5(-4,-0.8) L6(-3.2,-0.8) L7(-2.4,-0.8) L8(-1.6,-0.8) L9(-0.8,-0.8) L10(0,-0.8) L11(0.8,-0.8) L12(1.6,-0.8) L13(2.4,-0.8) L15(4,-0.8) L17(5.6,-0.8) L18(6.4,-0.8) L19(7.2,-0.8) M1(-7.2,-1.6) M2(-6.4,-1.6) M3(-5.6,-1.6) M5(-4,-1.6) M7(-2.4,-1.6) M8(-1.6,-1.6) M9(-0.8,-1.6) M10(0,-1.6) M11(0.8,-1.6) M12(1.6,-1.6) M13(2.4,-1.6) M14(3.2,-1.6) M15(4,-1.6) M17(5.6,-1.6) M18(6.4,-1.6) M19(7.2,-1.6) N1(-7.2,-2.4) N2(-6.4,-2.4) N3(-5.6,-2.4) N5(-4,-2.4) N7(-2.4,-2.4) N8(-1.6,-2.4) N9(-0.8,-2.4) N10(0,-2.4) N11(0.8,-2.4) N12(1.6,-2.4) N13(2.4,-2.4) N15(4,-2.4) N17(5.6,-2.4) N18(6.4,-2.4) N19(7.2,-2.4) P1(-7.2,-3.2) P2(-6.4,-3.2) P3(-5.6,-3.2) P5(-4,-3.2) P6(-3.2,-3.2) P9(-0.8,-3.2) P12(1.6,-3.2) P14(3.2,-3.2) P15(4,-3.2) P17(5.6,-3.2) P18(6.4,-3.2) P19(7.2,-3.2) R1(-7.2,-4) R2(-6.4,-4) R3(-5.6,-4) R6(-3.2,-4) R7(-2.4,-4) R8(-1.6,-4) R9(-0.8,-4) R10(0,-4) R11(0.8,-4) R12(1.6,-4) R13(2.4,-4) R14(3.2,-4) R17(5.6,-4) R18(6.4,-4) R19(7.2,-4) T1(-7.2,-4.8) T2(-6.4,-4.8) T3(-5.6,-4.8) T17(5.6,-4.8) T18(6.4,-4.8) T19(7.2,-4.8) U1(-7.2,-5.6) U2(-6.4,-5.6) U3(-5.6,-5.6) U4(-4.8,-5.6) U5(-4,-5.6) U6(-3.2,-5.6) U7(-2.4,-5.6) U8(-1.6,-5.6) U9(-0.8,-5.6) U10(0,-5.6) U11(0.8,-5.6) U12(1.6,-5.6) U13(2.4,-5.6) U14(3.2,-5.6) U15(4,-5.6) U16(4.8,-5.6) U17(5.6,-5.6) U18(6.4,-5.6) U19(7.2,-5.6) V1(-7.2,-6.4) V2(-6.4,-6.4) V3(-5.6,-6.4) V4(-4.8,-6.4) V5(-4,-6.4) V6(-3.2,-6.4) V7(-2.4,-6.4) V8(-1.6,-6.4) V9(-0.8,-6.4) V10(0,-6.4) V11(0.8,-6.4) V12(1.6,-6.4) V13(2.4,-6.4) V14(3.2,-6.4) V15(4,-6.4) V16(4.8,-6.4) V17(5.6,-6.4) V18(6.4,-6.4) V19(7.2,-6.4) W2(-6.4,-7.2) W3(-5.6,-7.2) W4(-4.8,-7.2) W5(-4,-7.2) W6(-3.2,-7.2) W7(-2.4,-7.2) W8(-1.6,-7.2) W9(-0.8,-7.2) W10(0,-7.2) W11(0.8,-7.2) W12(1.6,-7.2) W13(2.4,-7.2) W14(3.2,-7.2) W15(4,-7.2) W16(4.8,-7.2) W17(5.6,-7.2) W18(6.4,-7.2)
Top Overlay:
  circle w0.25: c-8.65,7.2 r0.125
  region: -7.284,8 -8,7.284 -8,8
  lines w0.2: -8,7.284 -7.284,8 ; -8,-8 8,-8 8,8 -8,8 -8,-8
Mechanical 13:
  lines w0.1: -8,-8 8,-8 8,8 -8,8 -8,-8
Mechanical 15:
  lines w0.1: -0.5,0 0.5,0 ; 0,-0.5 0,0.5 ; -9,-9 9,-9 9,9 -9,9 -9,-9
3D body: height 1.4, standoff 0, extent -8,-8 8,8

## BGA80P19X19-332 [mm] "BGA, 332-Leads, Body 17x17mm, Pitch 0.8mm"
height 2.6
pads (332):
  round 0.45 smd: A2(-6.4,7.2) A3(-5.6,7.2) A4(-4.8,7.2) A5(-4,7.2) A6(-3.2,7.2) A7(-2.4,7.2) A8(-1.6,7.2) A9(-0.8,7.2) A10(0,7.2) A11(0.8,7.2) A12(1.6,7.2) A13(2.4,7.2) A14(3.2,7.2) A15(4,7.2) A16(4.8,7.2) A17(5.6,7.2) A18(6.4,7.2) B1(-7.2,6.4) B2(-6.4,6.4) B3(-5.6,6.4) B4(-4.8,6.4) B5(-4,6.4) B6(-3.2,6.4) B7(-2.4,6.4) B8(-1.6,6.4) B9(-0.8,6.4) B10(0,6.4) B11(0.8,6.4) B12(1.6,6.4) B13(2.4,6.4) B14(3.2,6.4) B15(4,6.4) B16(4.8,6.4) B17(5.6,6.4) B18(6.4,6.4) B19(7.2,6.4) C1(-7.2,5.6) C2(-6.4,5.6) C3(-5.6,5.6) C4(-4.8,5.6) C5(-4,5.6) C6(-3.2,5.6) C7(-2.4,5.6) C8(-1.6,5.6) C9(-0.8,5.6) C10(0,5.6) C11(0.8,5.6) C12(1.6,5.6) C13(2.4,5.6) C14(3.2,5.6) C15(4,5.6) C16(4.8,5.6) C17(5.6,5.6) C18(6.4,5.6) C19(7.2,5.6) D1(-7.2,4.8) D2(-6.4,4.8) D3(-5.6,4.8) D4(-4.8,4.8) D5(-4,4.8) D6(-3.2,4.8) D7(-2.4,4.8) D8(-1.6,4.8) D9(-0.8,4.8) D10(0,4.8) D11(0.8,4.8) D12(1.6,4.8) D13(2.4,4.8) D14(3.2,4.8) D15(4,4.8) D16(4.8,4.8) D17(5.6,4.8) D18(6.4,4.8) D19(7.2,4.8) E1(-7.2,4) E2(-6.4,4) E3(-5.6,4) E4(-4.8,4) E5(-4,4) E6(-3.2,4) E7(-2.4,4) E8(-1.6,4) E9(-0.8,4) E10(0,4) E11(0.8,4) E12(1.6,4) E13(2.4,4) E14(3.2,4) E15(4,4) E16(4.8,4) E17(5.6,4) E18(6.4,4) E19(7.2,4) F1(-7.2,3.2) F2(-6.4,3.2) F3(-5.6,3.2) F4(-4.8,3.2) F5(-4,3.2) F6(-3.2,3.2) F7(-2.4,3.2) F8(-1.6,3.2) F9(-0.8,3.2) F10(0,3.2) F11(0.8,3.2) F12(1.6,3.2) F13(2.4,3.2) F14(3.2,3.2) F15(4,3.2) F16(4.8,3.2) F17(5.6,3.2) F18(6.4,3.2) F19(7.2,3.2) G1(-7.2,2.4) G2(-6.4,2.4) G3(-5.6,2.4) G4(-4.8,2.4) G5(-4,2.4) G6(-3.2,2.4) G7(-2.4,2.4) G8(-1.6,2.4) G9(-0.8,2.4) G10(0,2.4) G11(0.8,2.4) G12(1.6,2.4) G13(2.4,2.4) G14(3.2,2.4) G15(4,2.4) G16(4.8,2.4) G17(5.6,2.4) G18(6.4,2.4) G19(7.2,2.4) H1(-7.2,1.6) H2(-6.4,1.6) H3(-5.6,1.6) H4(-4.8,1.6) H5(-4,1.6) H6(-3.2,1.6) H7(-2.4,1.6) H13(2.4,1.6) H14(3.2,1.6) H15(4,1.6) H16(4.8,1.6) H17(5.6,1.6) H18(6.4,1.6) H19(7.2,1.6) J1(-7.2,0.8) J2(-6.4,0.8) J3(-5.6,0.8) J4(-4.8,0.8) J5(-4,0.8) J6(-3.2,0.8) J7(-2.4,0.8) J13(2.4,0.8) J14(3.2,0.8) J15(4,0.8) J16(4.8,0.8) J17(5.6,0.8) J18(6.4,0.8) J19(7.2,0.8) K1(-7.2,0) K2(-6.4,0) K3(-5.6,0) K4(-4.8,0) K5(-4,0) K6(-3.2,0) K7(-2.4,0) K13(2.4,0) K14(3.2,0) K15(4,0) K16(4.8,0) K17(5.6,0) K18(6.4,0) K19(7.2,0) L1(-7.2,-0.8) L2(-6.4,-0.8) L3(-5.6,-0.8) L4(-4.8,-0.8) L5(-4,-0.8) L6(-3.2,-0.8) L7(-2.4,-0.8) L13(2.4,-0.8) L14(3.2,-0.8) L15(4,-0.8) L16(4.8,-0.8) L17(5.6,-0.8) L18(6.4,-0.8) L19(7.2,-0.8) M1(-7.2,-1.6) M2(-6.4,-1.6) M3(-5.6,-1.6) M4(-4.8,-1.6) M5(-4,-1.6) M6(-3.2,-1.6) M7(-2.4,-1.6) M13(2.4,-1.6) M14(3.2,-1.6) M15(4,-1.6) M16(4.8,-1.6) M17(5.6,-1.6) M18(6.4,-1.6) M19(7.2,-1.6) N1(-7.2,-2.4) N2(-6.4,-2.4) N3(-5.6,-2.4) N4(-4.8,-2.4) N5(-4,-2.4) N6(-3.2,-2.4) N7(-2.4,-2.4) N8(-1.6,-2.4) N9(-0.8,-2.4) N10(0,-2.4) N11(0.8,-2.4) N12(1.6,-2.4) N13(2.4,-2.4) N14(3.2,-2.4) N15(4,-2.4) N16(4.8,-2.4) N17(5.6,-2.4) N18(6.4,-2.4) N19(7.2,-2.4) P1(-7.2,-3.2) P2(-6.4,-3.2) P3(-5.6,-3.2) P4(-4.8,-3.2) P5(-4,-3.2) P6(-3.2,-3.2) P7(-2.4,-3.2) P8(-1.6,-3.2) P9(-0.8,-3.2) P10(0,-3.2) P11(0.8,-3.2) P12(1.6,-3.2) P13(2.4,-3.2) P14(3.2,-3.2) P15(4,-3.2) P16(4.8,-3.2) P17(5.6,-3.2) P18(6.4,-3.2) P19(7.2,-3.2) R1(-7.2,-4) R2(-6.4,-4) R3(-5.6,-4) R4(-4.8,-4) R5(-4,-4) R6(-3.2,-4) R7(-2.4,-4) R8(-1.6,-4) R9(-0.8,-4) R10(0,-4) R11(0.8,-4) R12(1.6,-4) R13(2.4,-4) R14(3.2,-4) R15(4,-4) R16(4.8,-4) R17(5.6,-4) R18(6.4,-4) R19(7.2,-4) T1(-7.2,-4.8) T2(-6.4,-4.8) T3(-5.6,-4.8) T4(-4.8,-4.8) T5(-4,-4.8) T6(-3.2,-4.8) T7(-2.4,-4.8) T8(-1.6,-4.8) T9(-0.8,-4.8) T10(0,-4.8) T11(0.8,-4.8) T12(1.6,-4.8) T13(2.4,-4.8) T14(3.2,-4.8) T15(4,-4.8) T16(4.8,-4.8) T17(5.6,-4.8) T18(6.4,-4.8) T19(7.2,-4.8) U1(-7.2,-5.6) U2(-6.4,-5.6) U3(-5.6,-5.6) U4(-4.8,-5.6) U5(-4,-5.6) U6(-3.2,-5.6) U7(-2.4,-5.6) U8(-1.6,-5.6) U9(-0.8,-5.6) U10(0,-5.6) U11(0.8,-5.6) U12(1.6,-5.6) U13(2.4,-5.6) U14(3.2,-5.6) U15(4,-5.6) U16(4.8,-5.6) U17(5.6,-5.6) U18(6.4,-5.6) U19(7.2,-5.6) V1(-7.2,-6.4) V2(-6.4,-6.4) V3(-5.6,-6.4) V4(-4.8,-6.4) V5(-4,-6.4) V6(-3.2,-6.4) V7(-2.4,-6.4) V8(-1.6,-6.4) V9(-0.8,-6.4) V10(0,-6.4) V11(0.8,-6.4) V12(1.6,-6.4) V13(2.4,-6.4) V14(3.2,-6.4) V15(4,-6.4) V16(4.8,-6.4) V17(5.6,-6.4) V18(6.4,-6.4) V19(7.2,-6.4) W2(-6.4,-7.2) W3(-5.6,-7.2) W4(-4.8,-7.2) W5(-4,-7.2) W6(-3.2,-7.2) W7(-2.4,-7.2) W8(-1.6,-7.2) W9(-0.8,-7.2) W10(0,-7.2) W11(0.8,-7.2) W12(1.6,-7.2) W13(2.4,-7.2) W14(3.2,-7.2) W15(4,-7.2) W16(4.8,-7.2) W17(5.6,-7.2) W18(6.4,-7.2)
Top Overlay:
  circle w0.25: c-9.15,7.2 r0.125
  region: -7.5,8.5 -8.5,7.5 -8.5,8.5
  lines w0.2: -8.5,7.5 -7.5,8.5 ; -8.5,-8.5 -8.5,8.5 8.5,8.5 8.5,-8.5 -8.5,-8.5
Mechanical 13:
  lines w0.1: -8.5,-8.5 -8.5,8.5 8.5,8.5 8.5,-8.5 -8.5,-8.5
Mechanical 15:
  lines w0.1: -0.5,0 0.5,0 ; 0,-0.5 0,0.5 ; -9.5,-9.5 -9.5,9.5 9.5,9.5 9.5,-9.5 -9.5,-9.5
3D body: height 2.6, standoff 0, extent -8.5,-8.5 8.5,8.5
